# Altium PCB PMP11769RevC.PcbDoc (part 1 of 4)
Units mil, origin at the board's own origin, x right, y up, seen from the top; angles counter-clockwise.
Board outline 7800 x 8510 mil, 4 copper layers (Top, Inner Top, Inner Bottom, Bottom), stack 33.235 mil thick; 451 components, 226 nets, 1199 pads, 1742 vias.
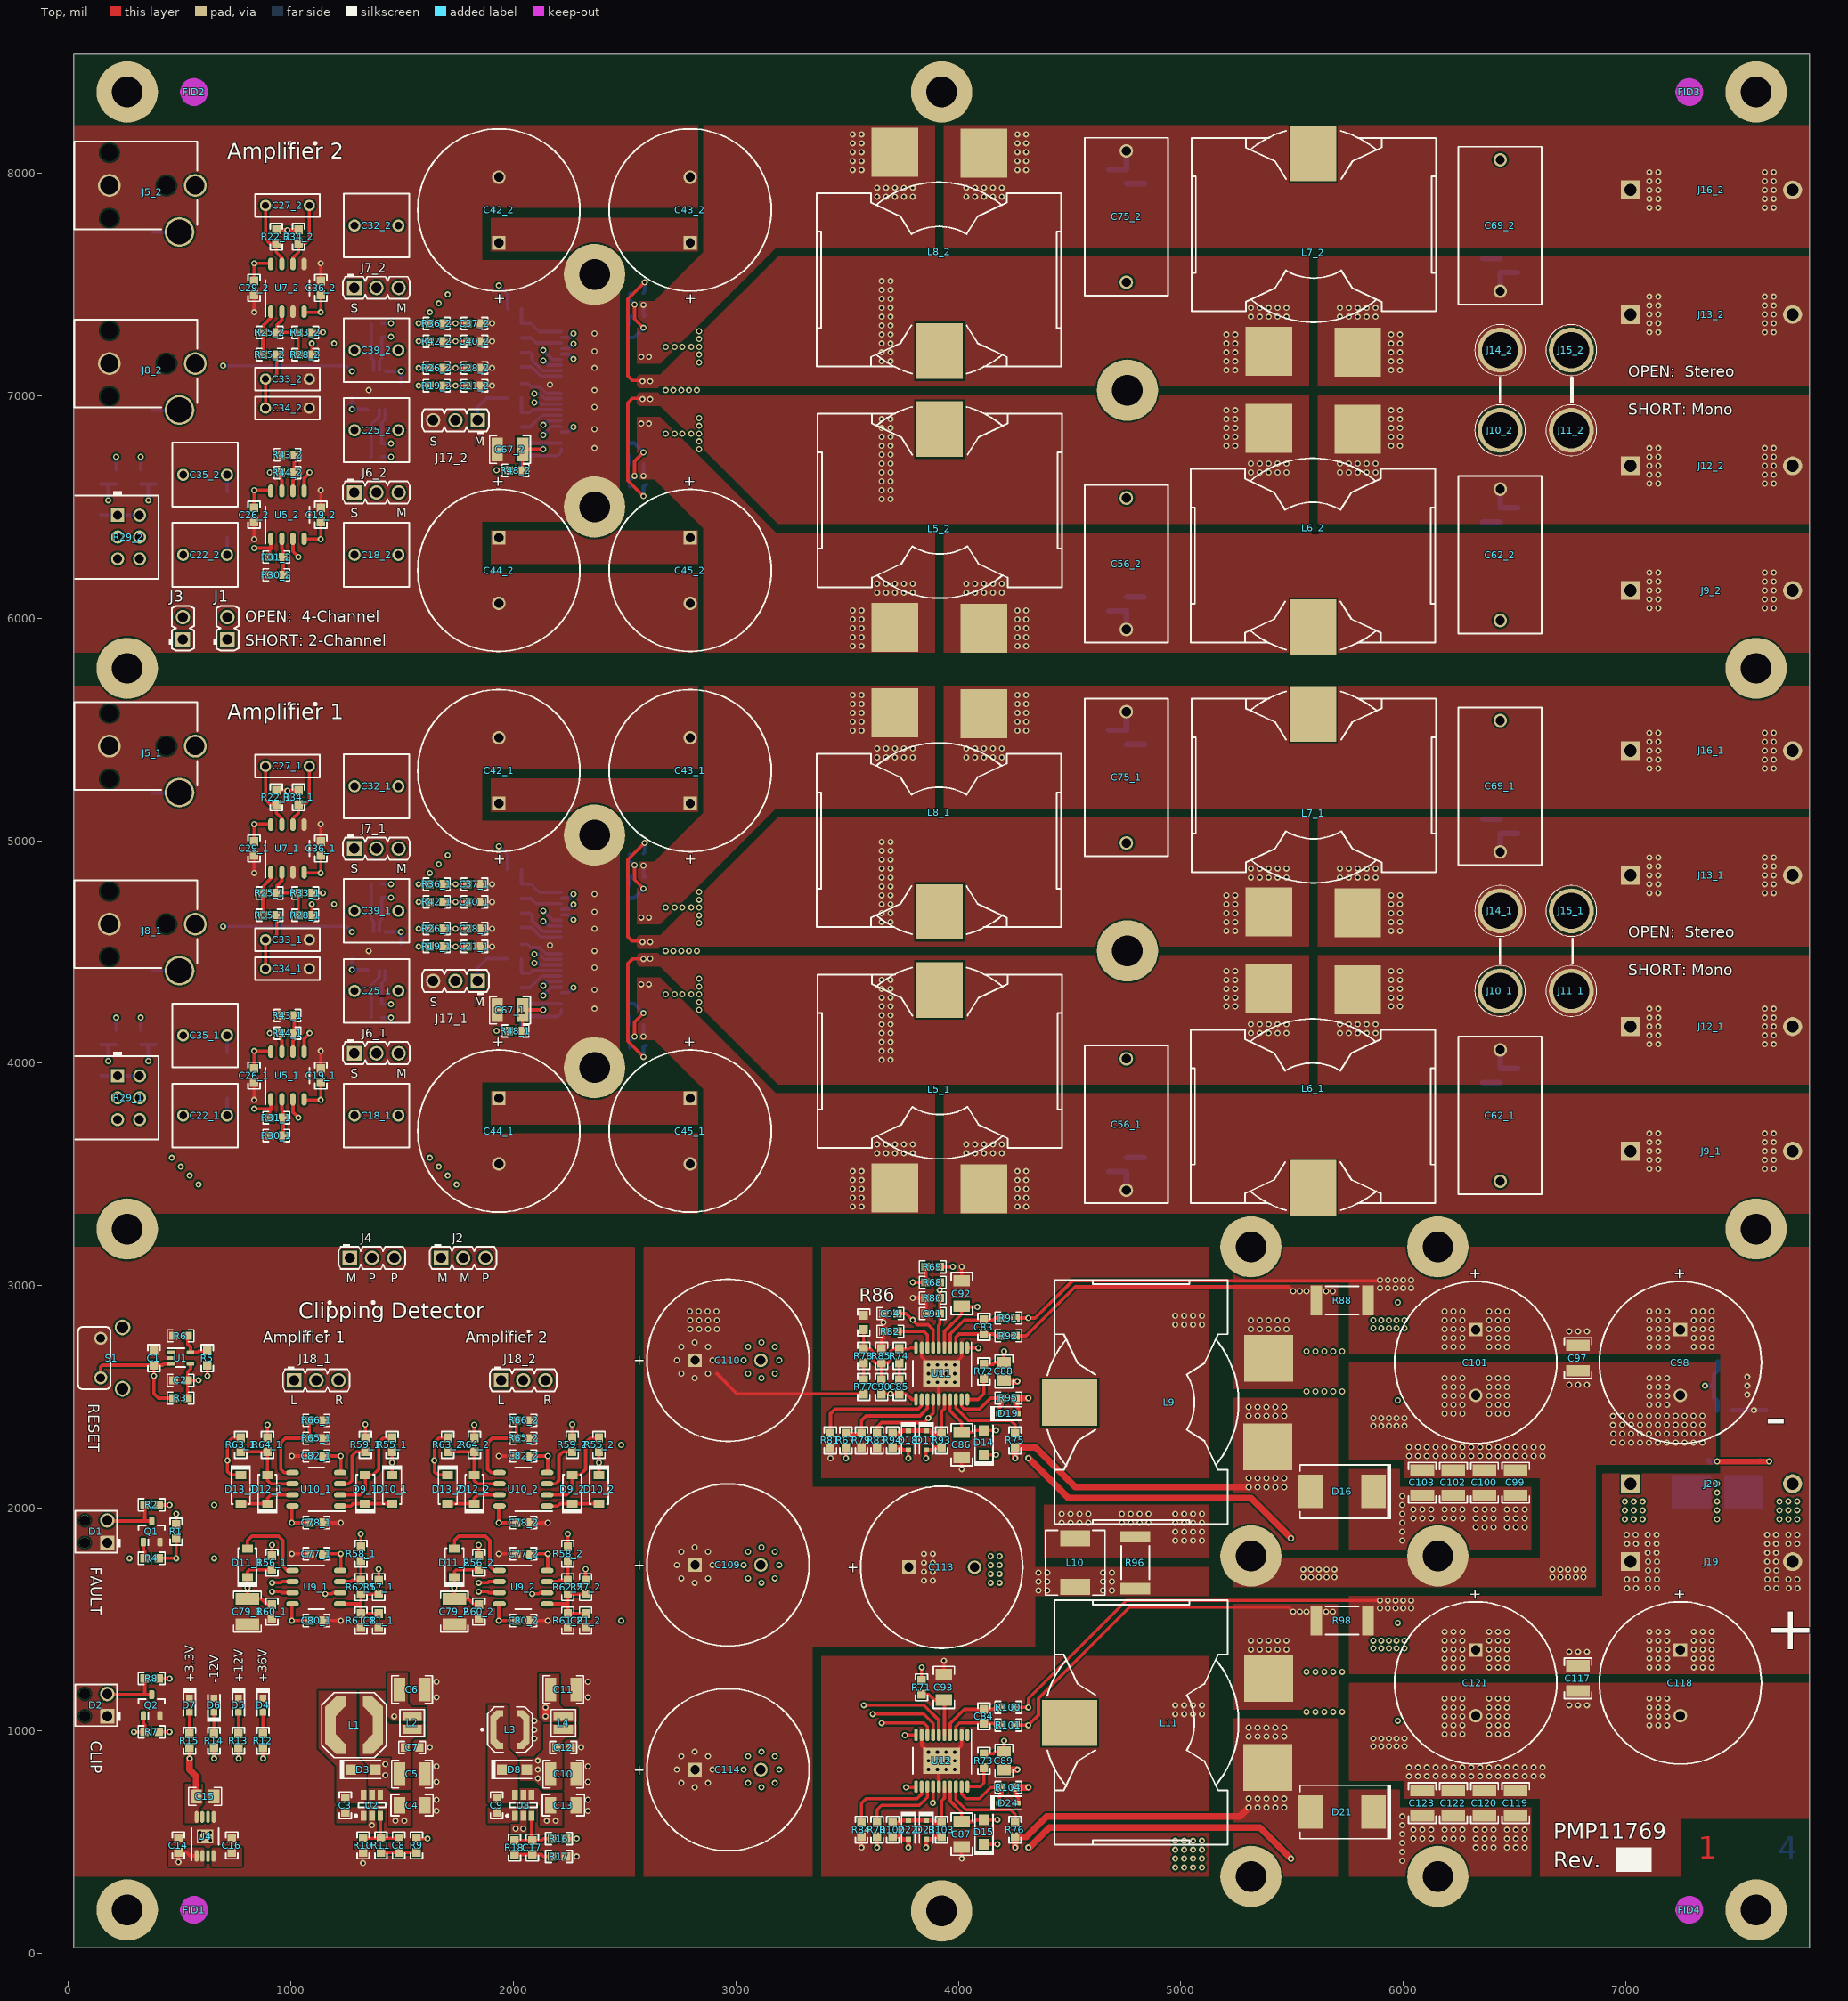
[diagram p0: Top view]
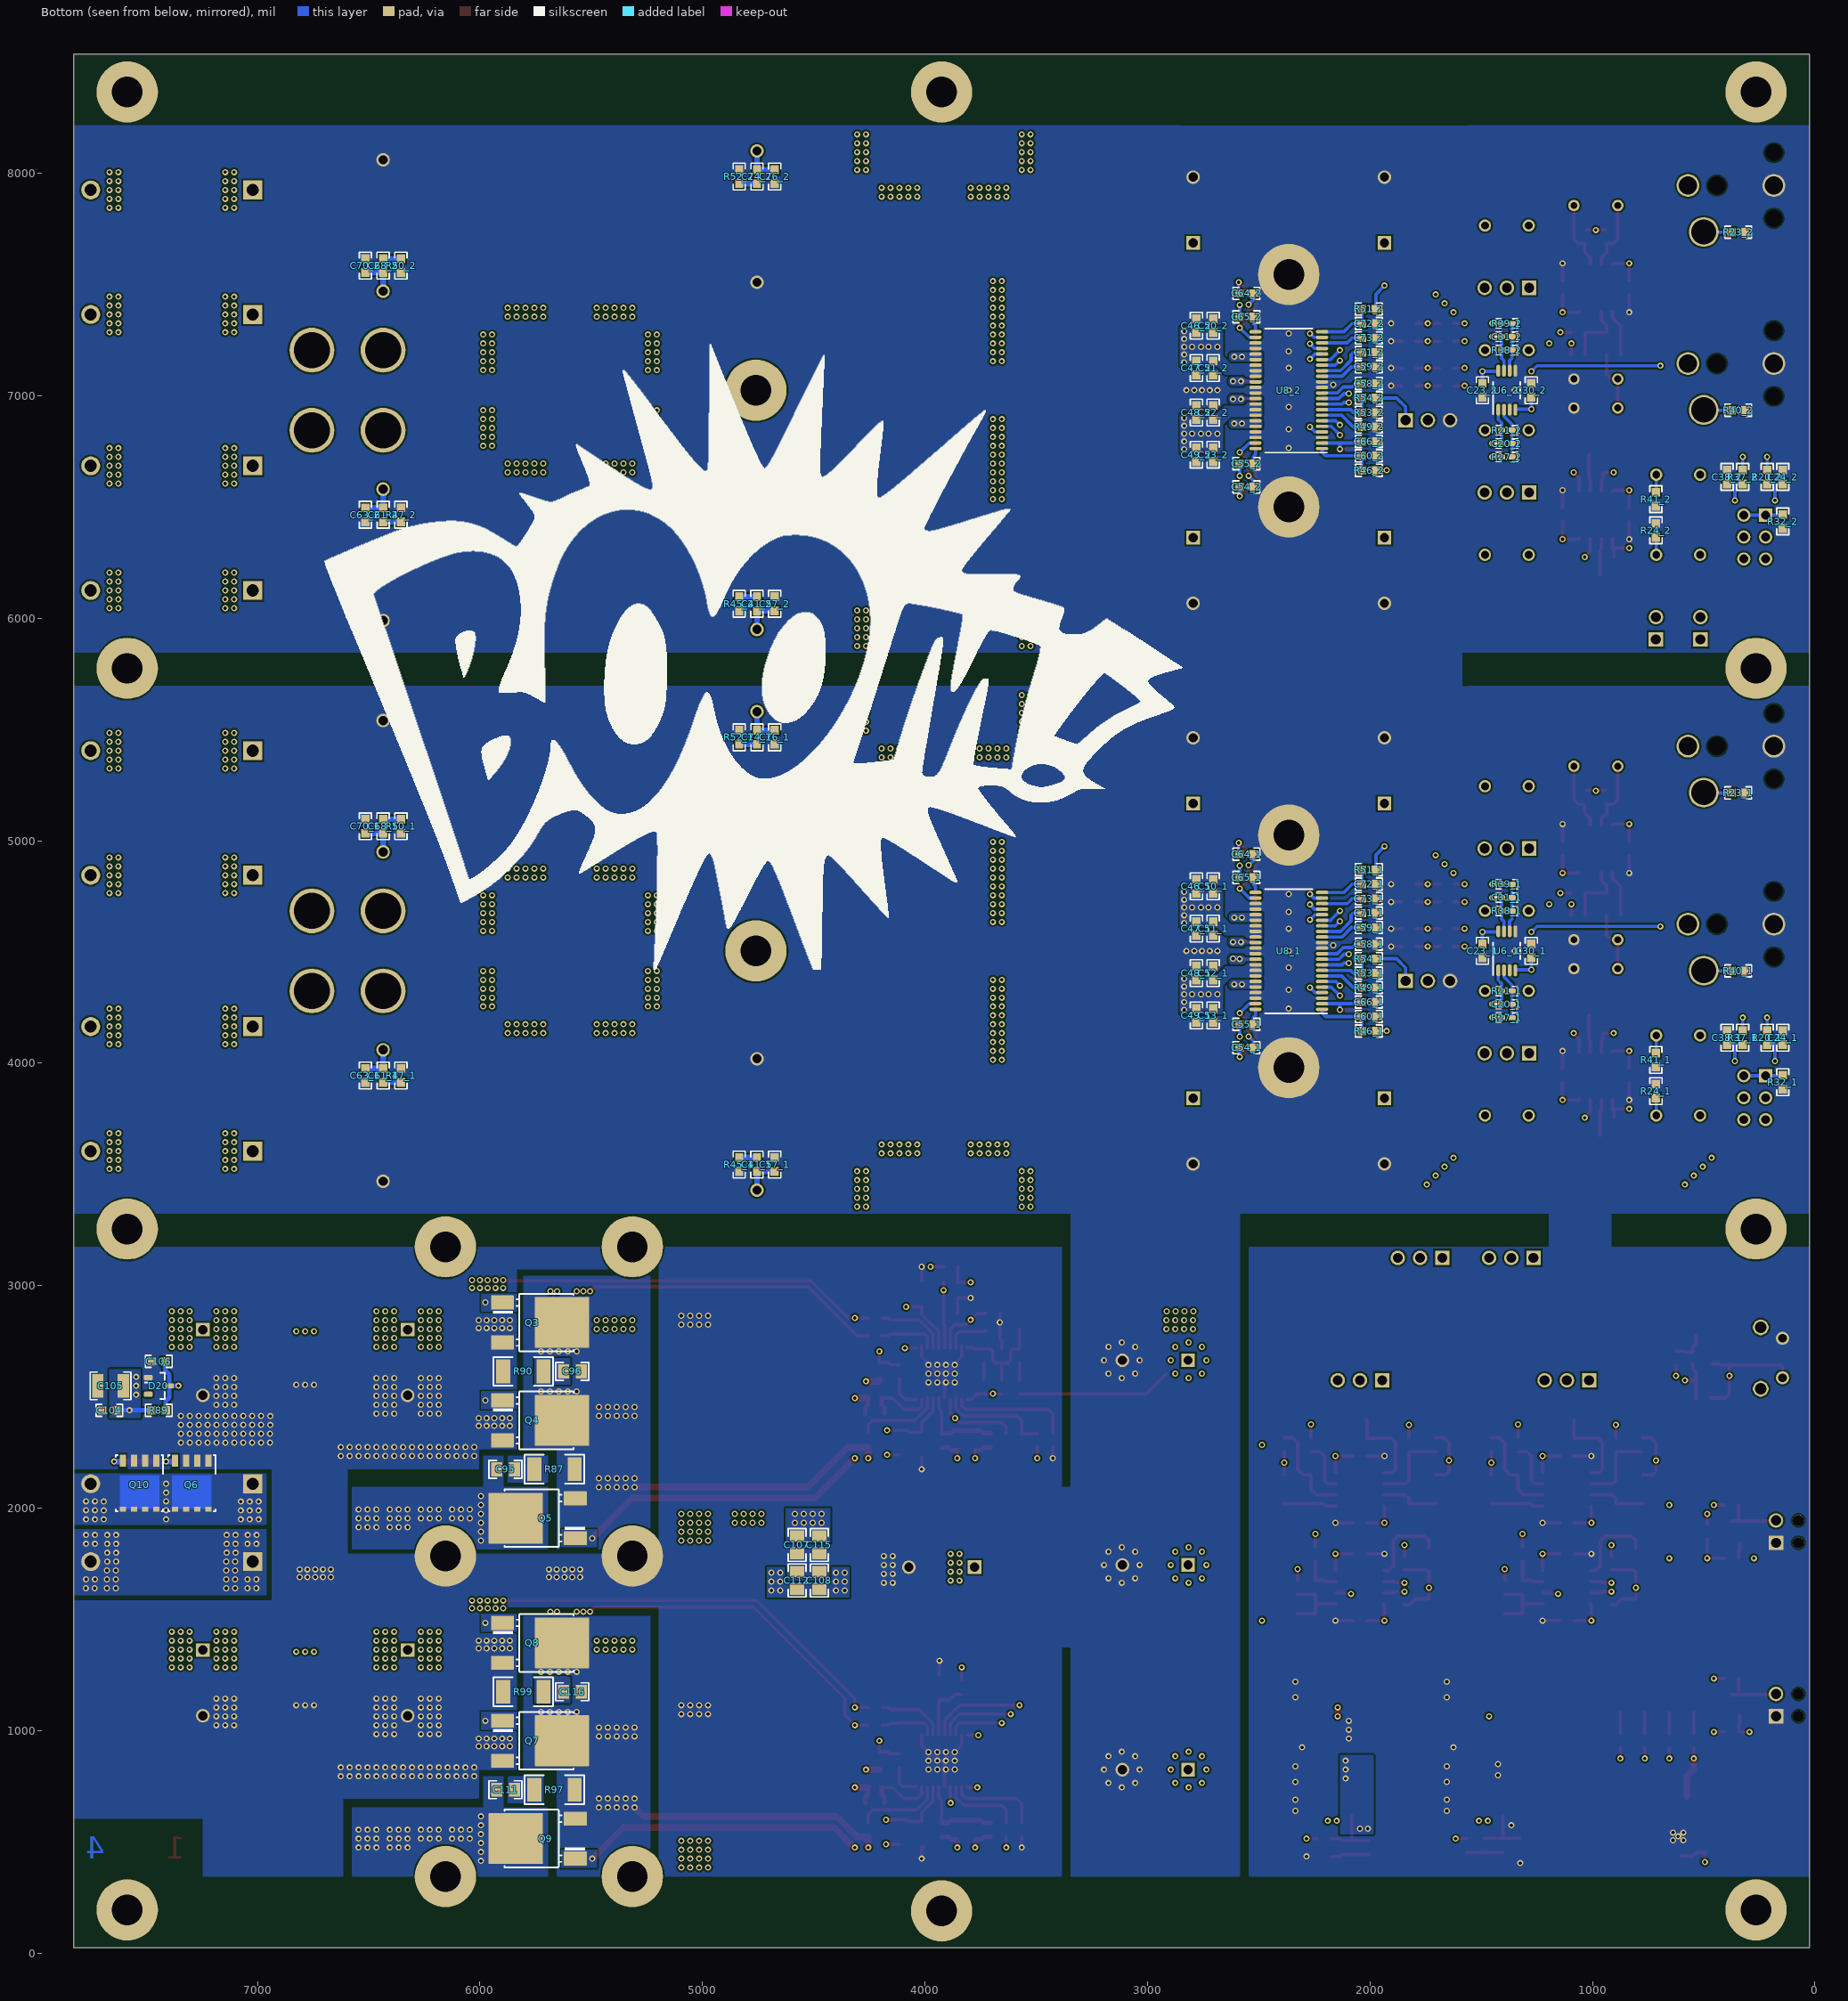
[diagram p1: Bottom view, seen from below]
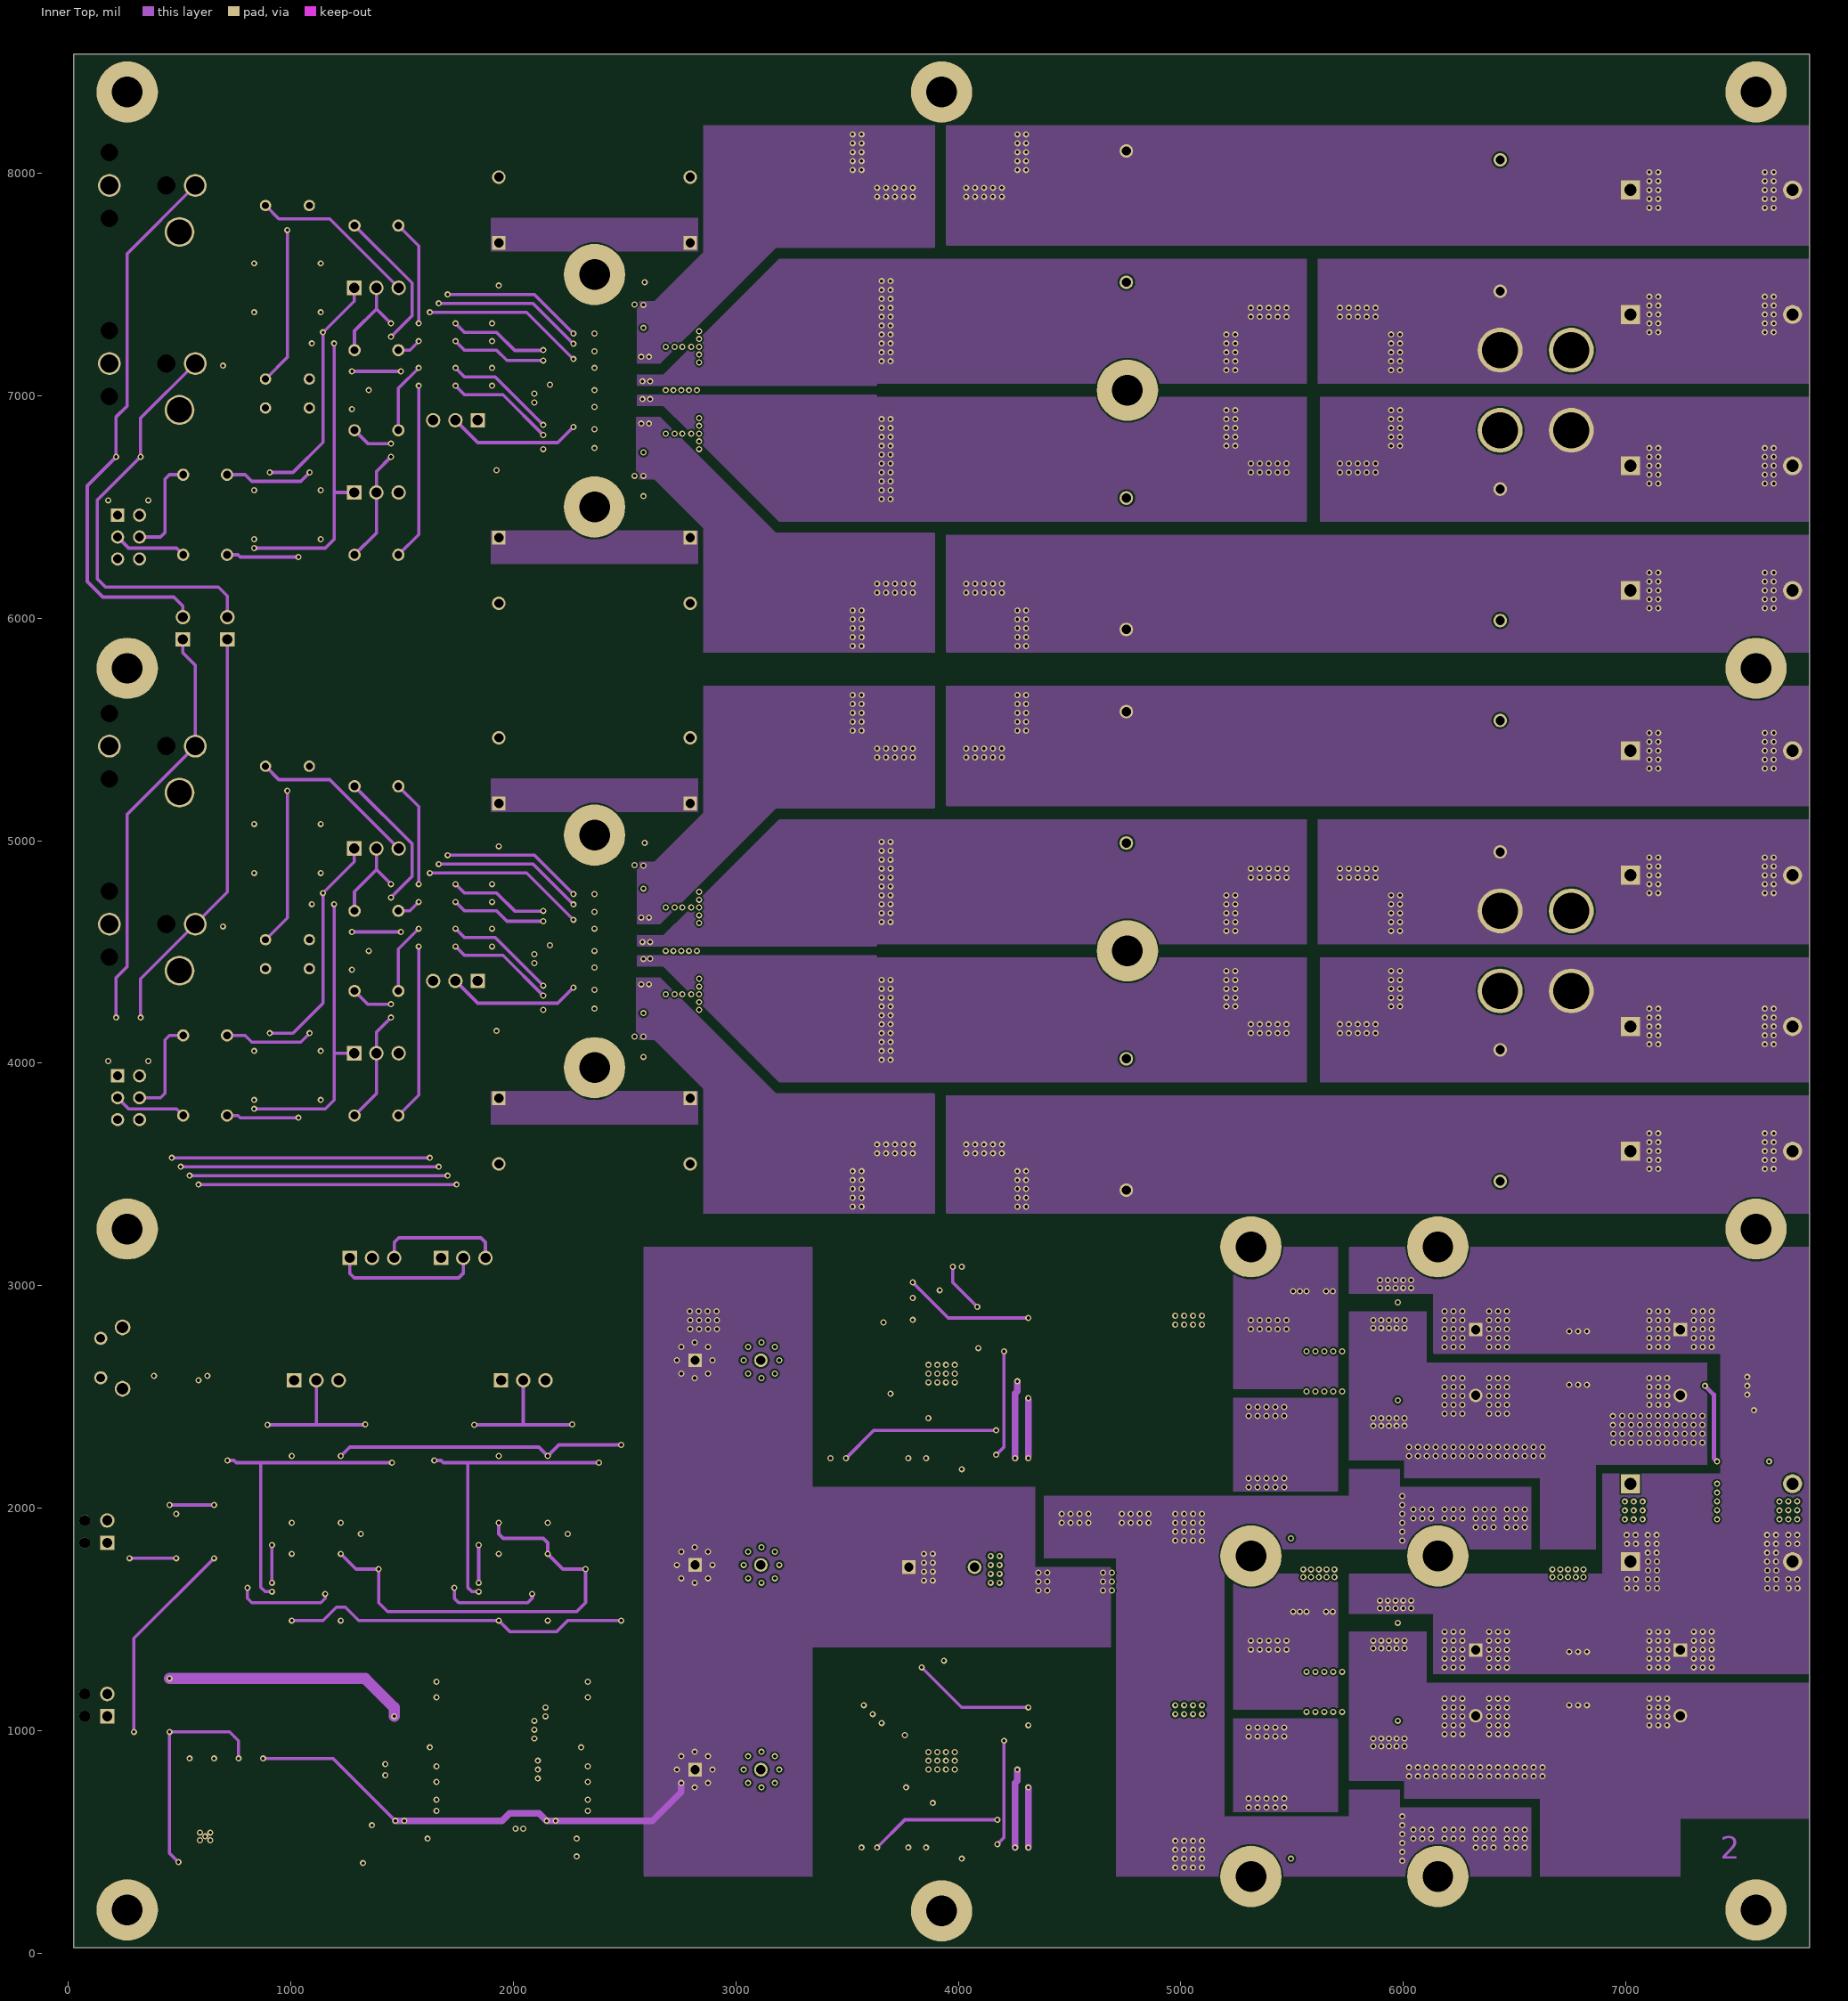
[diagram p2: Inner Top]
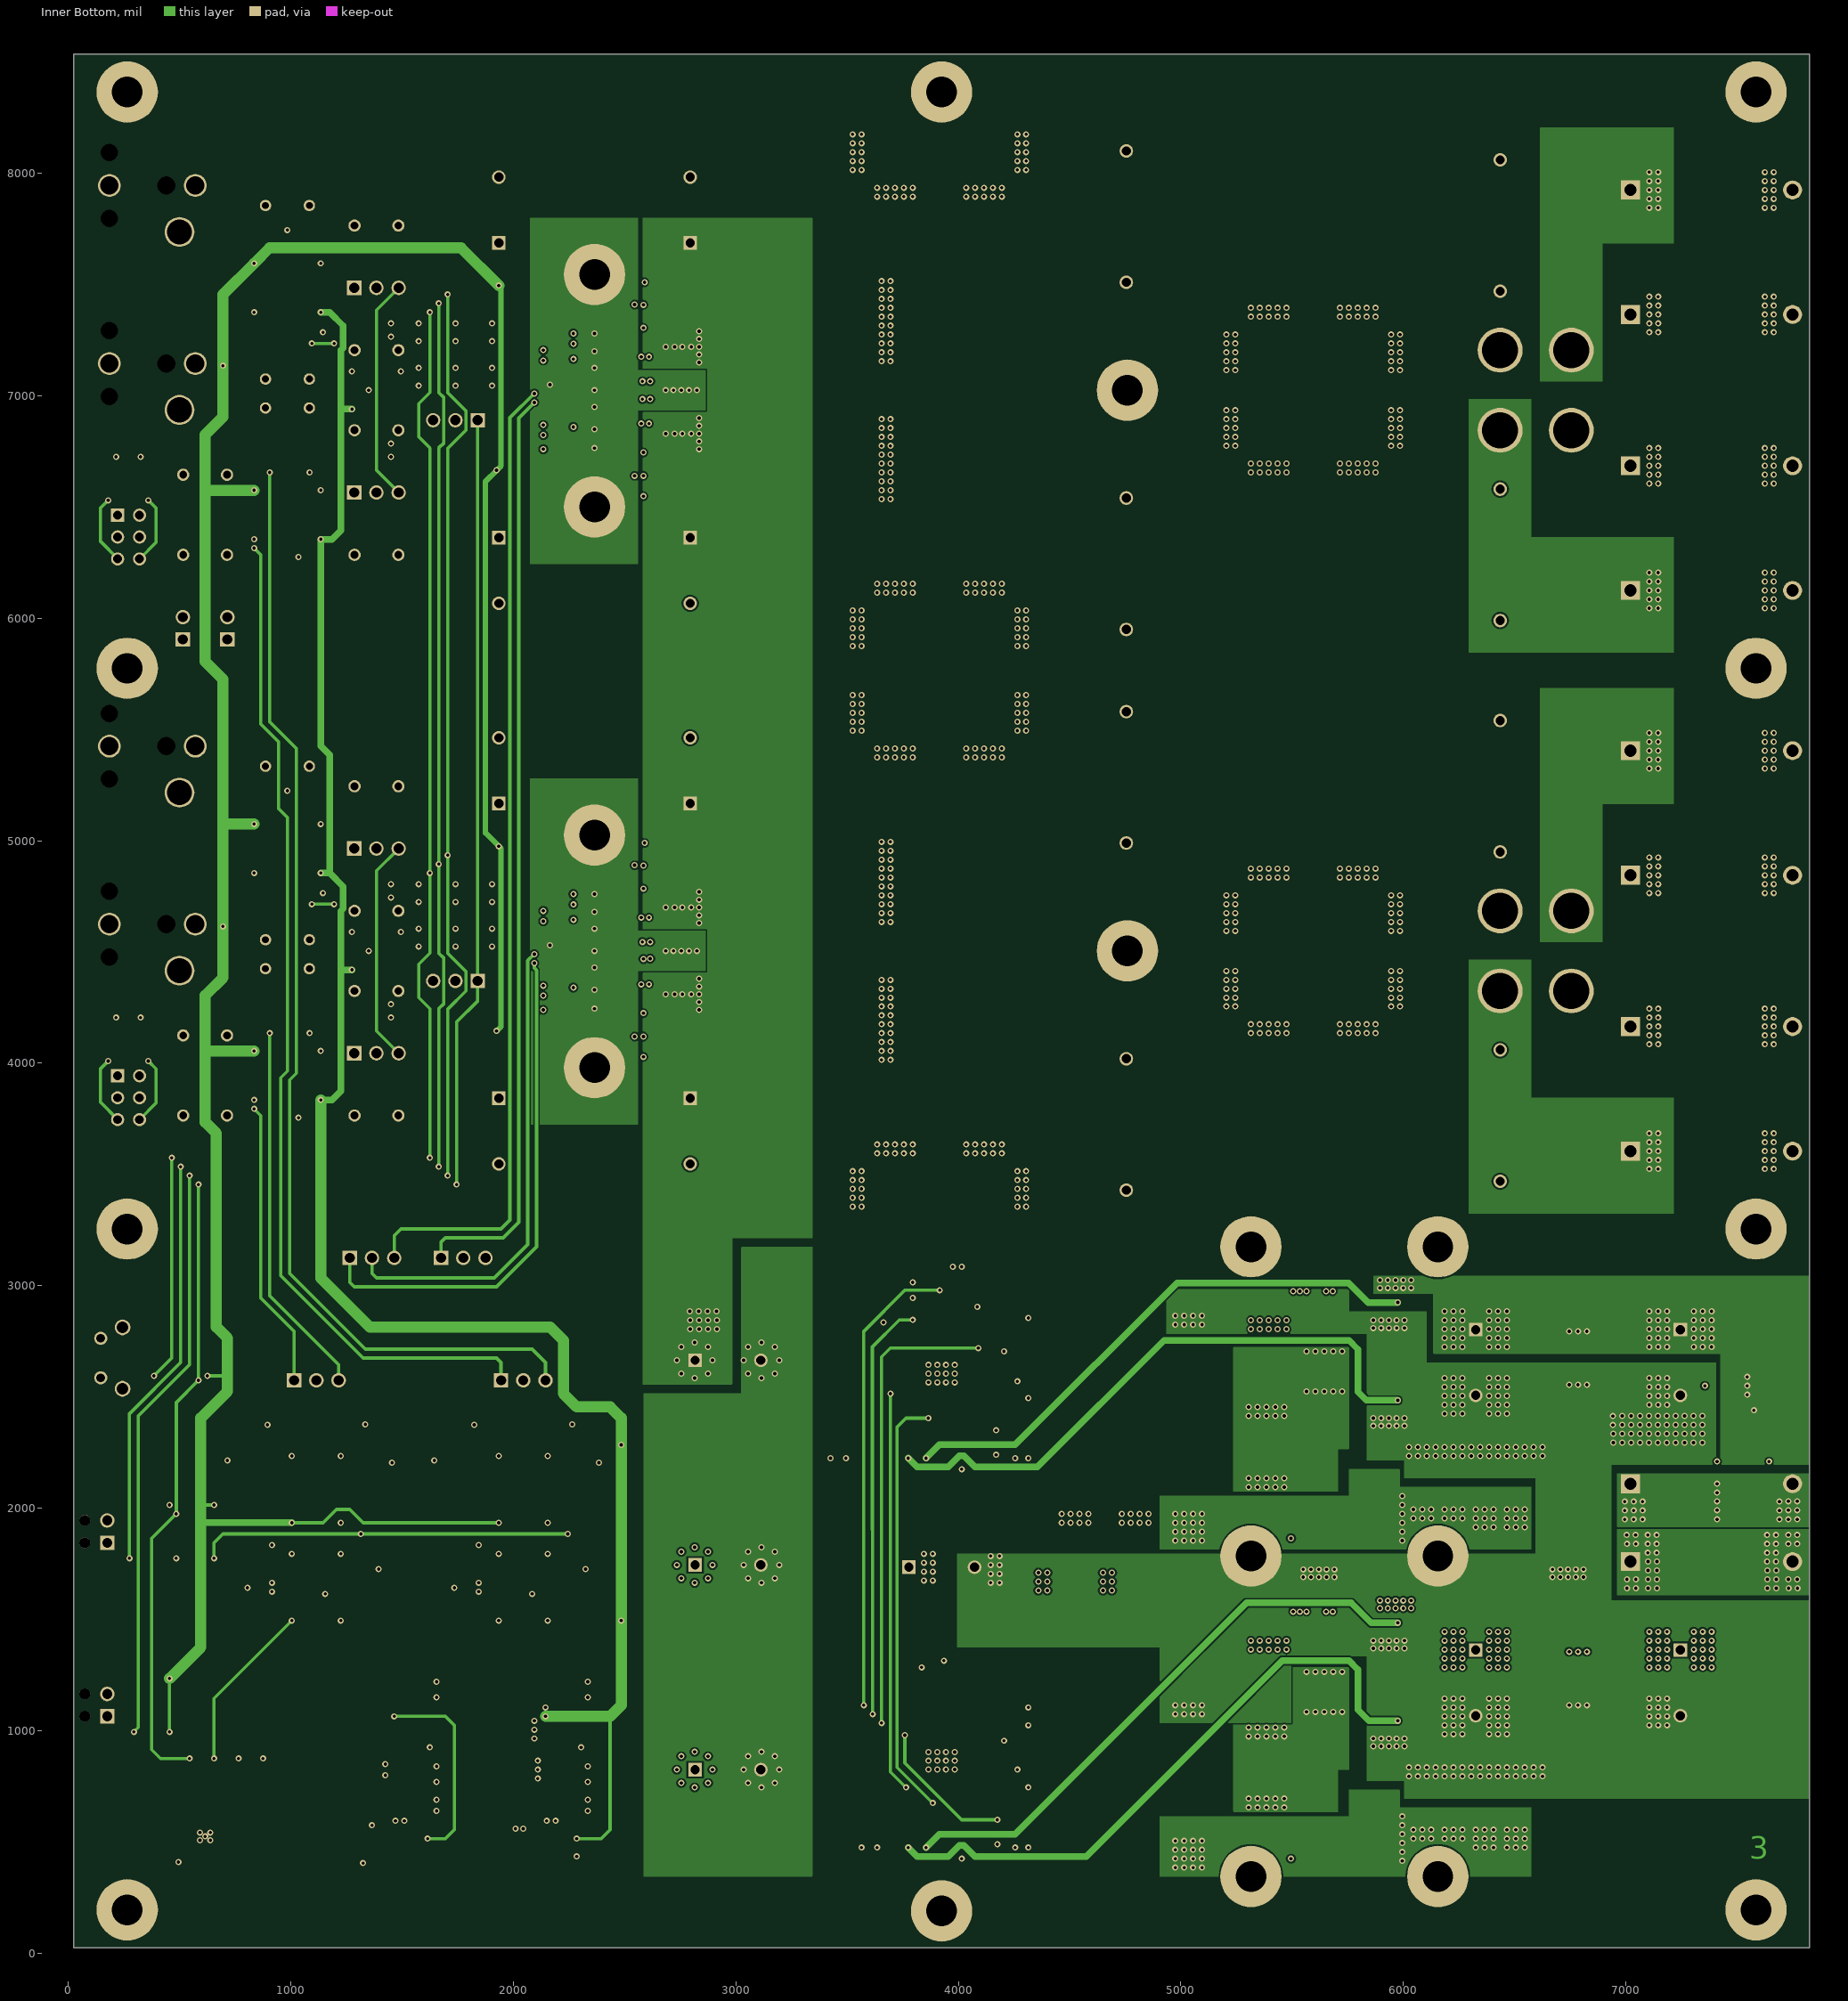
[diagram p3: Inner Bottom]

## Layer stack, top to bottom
Top Solder: solder mask 0.4, Solder Resist, Dk 3.5
Top: signal copper 1.4
Dielectric 1: core 12.6, FR-4, Dk 4.8
Inner Top: signal copper 1.4173
Dielectric 3: prepreg 5, Dk 4.2
Inner Bottom: signal copper 1.4173
Dielectric 2: core 10, Dk 4.2
Bottom: signal copper 1.4
Bottom Solder: solder mask 0.4, Solder Resist, Dk 3.5

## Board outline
25,25 25,8535 7825,8535 7825,25

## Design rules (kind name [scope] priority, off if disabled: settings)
Clearance [All] p1: gap=7.87
ComponentClearance [All] p1: gap=10 collisioncheckmode=3 verticalgap=10 showdistances=TRUE
DiffPairsRouting [All] p1: maxlimit=393.7 minlimit=4.92 mostfreqgap=5.91 toplayer_minwidth=15 toplayer_maxwidth=15 toplayer_prefwidth=15 midlayer1_minwidth=15 midlayer1_maxwidth=15 midlayer1_prefwidth=15 midlayer2_minwidth=15 midlayer2_maxwidth=15 midlayer2_prefwidth=15 bottomlayer_minwidth=15 bottomlayer_maxwidth=15 bottomlayer_prefwidth=15 maxuncoupledlength=500
FabricationTestPointUsage FabricationTestPointUsage_1 [All] p1: valid=0 allowmultiple=FALSE
FabricationTestpoint FabricationTestpoint_1 [All] p1: side=3 testpointundercomponent=TRUE minsize=40 maxsize=100 preferedsize=60 minholesize=0 maxholesize=40 preferedholesize=32 testpointgrid=1 allowsidetop=TRUE allowsidebottom=TRUE usegrid=TRUE gridtolerance=0.01
Height [All] p1: minheight=0 maxheight=1000.79 prefheight=500
HoleSize [All] p1: absolutevalues=TRUE maxlimit=236.22 minlimit=11.81 maxpercent=80.000 minpercent=20.000
HoleSize FabricationTestpoint [All] p2 off: absolutevalues=TRUE maxlimit=100 minlimit=1 maxpercent=80.000 minpercent=20.000
HoleSize FabricationTestPointUsage [All] p3 off: absolutevalues=TRUE maxlimit=100 minlimit=1 maxpercent=80.000 minpercent=20.000
MinimumAnnularRing [All] p1: minimumring=5.91
MinimumSolderMaskSliver [All] p1: minsoldermaskwidth=1
PlaneClearance [All] p1: clearance=19.68
PlaneConnect [All] p1: planeconnectstyle=Direct reliefexpansion=15.75 reliefentries=4 reliefconductorwidth=5.91 reliefairgap=5.91
PolygonConnect [All] p1: connectstyle=Direct reliefconductorwidth=5.91 reliefentries=4 polygonreliefangle="90 Angle" airgapwidth=10
RoomDefinition 2 [InComponentClass('2')] p1: confinementstyle=ConfineIn formatcopy=TRUE lockcomponents=FALSE outline -585,5825 7870,5825 7870,8235 -585,8235
RoomDefinition 1 [InComponentClass('1')] p2: confinementstyle=ConfineIn formatcopy=TRUE lockcomponents=FALSE outline -585,3305 7870,3305 7870,5715 -585,5715
RoutingCorners [All] p1: cornerstyle=45-Degree minsetback=49.21 maxsetback=49.21
RoutingVias [All] p1: holewidth=11.81 width=27.56 viastyle="Through Hole" minholewidth=11.81 minwidth=19.68 maxholewidth=39.37 maxwidth=59.06
SilkToSilkClearance [All] p1: silktosilkclearance=3.94
SilkToSolderMaskClearance SilkscreenOverComponentPads [IsPad] p1: minsilkscreentomaskgap=5 clearancetoexposedcopper=TRUE
SolderMaskExpansion [All] p1: expansion=2.95
UnpouredPolygon [All] p1: allowunpoured=FALSE
Width [All] p1: maxlimit=393.7 minlimit=4.92 preferedwidth=10 toplayer_minwidth=5.91 midlayer1_prefwidth=5.91 midlayer2_prefwidth=5.91 bottomlayer_minwidth=5.91 minimp=50.000000 maximp=50.000000 favimp=50.000000
17 further rules are at their usual default settings.

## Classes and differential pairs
channel class "PMP11769Revc - Clipping Detector": 1 2
channel class "PMP11769RevC - Amplifier": 1 2
net class OSC_IOP[1..2]: OSC_IOP1 OSC_IOP2
net class OSC_IOM[1..2]: OSC_IOM1 OSC_IOM2
net class IN_R[1..2]: IN_R1 IN_R2
net class IN_L[1..2]: IN_L1 IN_L2
component class 2: C18_2 C19_2 C20_2 C21_2 C22_2 C23_2 C24_2 C25_2 C26_2 C27_2 C28_2 C29_2 C30_2 C31_2 C32_2 C33_2 C34_2 C35_2 C36_2 C37_2 C38_2 C39_2 C40_2 C41_2 C42_2 C43_2 C44_2 C45_2 C46_2 C47_2 C48_2 C49_2 C50_2 C51_2 C52_2 C53_2 C54_2 C55_2 C56_2 C57_2 C58_2 C59_2 C60_2 C61_2 C62_2 C63_2 C64_2 C65_2 C66_2 C67_2 C68_2 C69_2 C70_2 C71_2 C72_2 C73_2 C74_2 C75_2 C76_2 J5_2 J6_2 J7_2 J8_2 J9_2 J10_2 J11_2 J12_2 J13_2 J14_2 J15_2 J16_2 J17_2 L5_2 L6_2 L7_2 L8_2 R19_2 R20_2 R21_2 R22_2 R23_2 R24_2 R25_2 R26_2 R27_2 R28_2 R29_2 R30_2 R31_2 R32_2 R33_2 R34_2 R35_2 R36_2 R37_2 R38_2 R39_2 R40_2 R41_2 R42_2 R43_2 R44_2 R45_2 R46_2 R47_2 R48_2 R49_2 R50_2 R51_2 R52_2 R53_2 R54_2 U5_2 U6_2 U7_2 U8_2
component class 1: C18_1 C19_1 C20_1 C21_1 C22_1 C23_1 C24_1 C25_1 C26_1 C27_1 C28_1 C29_1 C30_1 C31_1 C32_1 C33_1 C34_1 C35_1 C36_1 C37_1 C38_1 C39_1 C40_1 C41_1 C42_1 C43_1 C44_1 C45_1 C46_1 C47_1 C48_1 C49_1 C50_1 C51_1 C52_1 C53_1 C54_1 C55_1 C56_1 C57_1 C58_1 C59_1 C60_1 C61_1 C62_1 C63_1 C64_1 C65_1 C66_1 C67_1 C68_1 C69_1 C70_1 C71_1 C72_1 C73_1 C74_1 C75_1 C76_1 J5_1 J6_1 J7_1 J8_1 J9_1 J10_1 J11_1 J12_1 J13_1 J14_1 J15_1 J16_1 J17_1 L5_1 L6_1 L7_1 L8_1 R19_1 R20_1 R21_1 R22_1 R23_1 R24_1 R25_1 R26_1 R27_1 R28_1 R29_1 R30_1 R31_1 R32_1 R33_1 R34_1 R35_1 R36_1 R37_1 R38_1 R39_1 R40_1 R41_1 R42_1 R43_1 R44_1 R45_1 R46_1 R47_1 R48_1 R49_1 R50_1 R51_1 R52_1 R53_1 R54_1 U5_1 U6_1 U7_1 U8_1
net class BUFF_L[1..2]: BUFF_L1 BUFF_L2
net class BUFF_R[1..2]: BUFF_R1 BUFF_R2

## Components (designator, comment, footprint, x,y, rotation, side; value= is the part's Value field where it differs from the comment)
C1 "C1608X7R1E105K080AB" 0603 385,2675 r90 top
C2 "C1608X7R1H104K" 0603 505,2575 r0 top
C3 "C1608X7R1H104K" 0603 1245,665 r270 top
C4 "C3216X7R1H105K" 1206 1545,665 r0 top
C5 "C3225X7R1E106M" 1210 1545,805 r0 top
C6 "C3225X7R1E106M" 1210 1545,1185 r0 top
C7 "C1608X7R1H104K" 0603 1545,925 r180 top
C8 "C1608C0G1H221J" 0603 1485,485 r90 top
C9 "C1608X7R1H104K" 0603 1925,665 r270 top
C10 "C3225X7R1E106M" 1210 2225,805 r180 top
C11 "C3225X7R1E106M" 1210 2225,1185 r180 top
C12 "C1608X7R1H104K" 0603 2225,925 r0 top
C13 "C3216X7R1H105K" 1206 2225,665 r0 top
C14 "C1608X7R1E105K080AB" 0603 495,485 r90 top
C15 "C2012X7R1A475M" 0805_HV 615,705 r0 top
C16 "C1608X7R1H102K" 0603 735,485 r90 top
C17 "C1608C0G1H221J" 0603 2085,475 r90 top
C18_1 "R82CC4470Z330J" R82_720x720x1300 1385,3765 r180 top (schematic designator C18)
C18_2 "R82CC4470Z330J" R82_720x720x1300 1385,6285 r180 top (schematic designator C18)
C19_1 "C1608X7R1H104K" 0603 1135,3945 r90 top (schematic designator C19)
C19_2 "C1608X7R1H104K" 0603 1135,6465 r90 top (schematic designator C19)
C20_1 "C1005C0G1H220J050BA" 0402 1385,4265 r180 bottom (schematic designator C20)
C20_2 "C1005C0G1H220J050BA" 0402 1385,6785 r180 bottom (schematic designator C20)
C21_1 "C1608C0G1H101J" 0603 1825,4525 r0 top (schematic designator C21)
C21_2 "C1608C0G1H101J" 0603 1825,7045 r0 top (schematic designator C21)
C22_1 "R82CC4470Z330J" R82_720x720x1300 615,3765 r180 top (schematic designator C22)
C22_2 "R82CC4470Z330J" R82_720x720x1300 615,6285 r180 top (schematic designator C22)
C23_1 "C1608X7R1H104K" 0603 1495,4505 r270 bottom (schematic designator C23)
C23_2 "C1608X7R1H104K" 0603 1495,7025 r270 bottom (schematic designator C23)
C24_1 "C1608C0G1H101J" 0603 145,4115 r90 bottom (schematic designator C24)
C24_2 "C1608C0G1H101J" 0603 145,6635 r90 bottom (schematic designator C24)
C25_1 "R82CC4470Z330J" R82_720x720x1300 1385,4325 r180 top (schematic designator C25)
C25_2 "R82CC4470Z330J" R82_720x720x1300 1385,6845 r180 top (schematic designator C25)
C26_1 "C1608X7R1H104K" 0603 835,3945 r270 top (schematic designator C26)
C26_2 "C1608X7R1H104K" 0603 835,6465 r270 top (schematic designator C26)
C27_1 "R82DC3100DQ50J" R82_720x250x650 985,5335 r0 top (schematic designator C27)
C27_2 "R82DC3100DQ50J" R82_720x250x650 985,7855 r0 top (schematic designator C27)
C28_1 "C1608C0G1H101J" 0603 1825,4605 r0 top (schematic designator C28)
C28_2 "C1608C0G1H101J" 0603 1825,7125 r0 top (schematic designator C28)
C29_1 "C1608X7R1H104K" 0603 835,4965 r270 top (schematic designator C29)
C29_2 "C1608X7R1H104K" 0603 835,7485 r270 top (schematic designator C29)
C30_1 "C1608X7R1H104K" 0603 1275,4505 r90 bottom (schematic designator C30)
C30_2 "C1608X7R1H104K" 0603 1275,7025 r90 bottom (schematic designator C30)
C31_1 "C1005C0G1H220J050BA" 0402 1385,4745 r180 bottom (schematic designator C31)
C31_2 "C1005C0G1H220J050BA" 0402 1385,7265 r180 bottom (schematic designator C31)
C32_1 "R82CC4470Z330J" R82_720x720x1300 1385,5245 r180 top (schematic designator C32)
C32_2 "R82CC4470Z330J" R82_720x720x1300 1385,7765 r180 top (schematic designator C32)
C33_1 "R82DC3220DQ60J" R82_720x250x650 985,4555 r0 top (schematic designator C33)
C33_2 "R82DC3220DQ60J" R82_720x250x650 985,7075 r0 top (schematic designator C33)
C34_1 "R82DC3150AA60J" R82_720x250x650 985,4425 r0 top (schematic designator C34)
C34_2 "R82DC3150AA60J" R82_720x250x650 985,6945 r0 top (schematic designator C34)
C35_1 "R82CC4470Z330J" R82_720x720x1300 615,4125 r180 top (schematic designator C35)
C35_2 "R82CC4470Z330J" R82_720x720x1300 615,6645 r180 top (schematic designator C35)
C36_1 "C1608X7R1H104K" 0603 1135,4965 r90 top (schematic designator C36)
C36_2 "C1608X7R1H104K" 0603 1135,7485 r90 top (schematic designator C36)
C37_1 "C1608C0G1H101J" 0603 1825,4805 r0 top (schematic designator C37)
C37_2 "C1608C0G1H101J" 0603 1825,7325 r0 top (schematic designator C37)
C38_1 "C1608C0G1H101J" 0603 395,4115 r90 bottom (schematic designator C38)
C38_2 "C1608C0G1H101J" 0603 395,6635 r90 bottom (schematic designator C38)
C39_1 "R82CC4470Z330J" R82_720x720x1300 1385,4685 r180 top (schematic designator C39)
C39_2 "R82CC4470Z330J" R82_720x720x1300 1385,7205 r180 top (schematic designator C39)
C40_1 "C1608C0G1H101J" 0603 1825,4725 r0 top (schematic designator C40)
C40_2 "C1608C0G1H101J" 0603 1825,7245 r0 top (schematic designator C40)
C41_1 "C1608X7R1H103K" 0603 4755,3545 r90 bottom (schematic designator C41)
C41_2 "C1608X7R1H103K" 0603 4755,6065 r90 bottom (schematic designator C41)
C42_1 "UPW1H821MHD6" PW_1800x2000 1935,5315 r90 top (schematic designator C42)
C42_2 "UPW1H821MHD6" PW_1800x2000 1935,7835 r90 top (schematic designator C42)
C43_1 "UPW1H821MHD6" PW_1800x2000 2795,5315 r90 top (schematic designator C43)
C43_2 "UPW1H821MHD6" PW_1800x2000 2795,7835 r90 top (schematic designator C43)
C44_1 "UPW1H821MHD6" PW_1800x2000 1935,3695 r270 top (schematic designator C44)
C44_2 "UPW1H821MHD6" PW_1800x2000 1935,6215 r270 top (schematic designator C44)
C45_1 "UPW1H821MHD6" PW_1800x2000 2795,3695 r270 top (schematic designator C45)
C45_2 "UPW1H821MHD6" PW_1800x2000 2795,6215 r270 top (schematic designator C45)
C46_1 "UMK107AB7105KA-T" 0603 2780,4795 r90 bottom (schematic designator C46)
C46_2 "UMK107AB7105KA-T" 0603 2780,7315 r90 bottom (schematic designator C46)
C47_1 "UMK107AB7105KA-T" 0603 2780,4605 r270 bottom (schematic designator C47)
C47_2 "UMK107AB7105KA-T" 0603 2780,7125 r270 bottom (schematic designator C47)
C48_1 "UMK107AB7105KA-T" 0603 2780,4405 r90 bottom (schematic designator C48)
C48_2 "UMK107AB7105KA-T" 0603 2780,6925 r90 bottom (schematic designator C48)
C49_1 "UMK107AB7105KA-T" 0603 2780,4215 r270 bottom (schematic designator C49)
C49_2 "UMK107AB7105KA-T" 0603 2780,6735 r270 bottom (schematic designator C49)
C50_1 "UMK107AB7105KA-T" 0603 2705,4795 r90 bottom (schematic designator C50)
C50_2 "UMK107AB7105KA-T" 0603 2705,7315 r90 bottom (schematic designator C50)
C51_1 "UMK107AB7105KA-T" 0603 2705,4605 r270 bottom (schematic designator C51)
C51_2 "UMK107AB7105KA-T" 0603 2705,7125 r270 bottom (schematic designator C51)
C52_1 "UMK107AB7105KA-T" 0603 2705,4405 r90 bottom (schematic designator C52)
C52_2 "UMK107AB7105KA-T" 0603 2705,6925 r90 bottom (schematic designator C52)
C53_1 "UMK107AB7105KA-T" 0603 2705,4215 r270 bottom (schematic designator C53)
C53_2 "UMK107AB7105KA-T" 0603 2705,6735 r270 bottom (schematic designator C53)
C54_1 "GRM188R71H333KA61D" 0603 2555,4070 r0 bottom (schematic designator C54)
C54_2 "GRM188R71H333KA61D" 0603 2555,6590 r0 bottom (schematic designator C54)
C55_1 "GRM188R71H333KA61D" 0603 2555,4175 r0 bottom (schematic designator C55)
C55_2 "GRM188R71H333KA61D" 0603 2555,6695 r0 bottom (schematic designator C55)
C56_1 "PHE426HB7100JR06" PHE426_1800x950x1750 4755,3725 r90 top (schematic designator C56)
C56_2 "PHE426HB7100JR06" PHE426_1800x950x1750 4755,6245 r90 top (schematic designator C56)
C57_1 "C1608C0G2A102J" 0603 4675,3545 r90 bottom (schematic designator C57)
C57_2 "C1608C0G2A102J" 0603 4675,6065 r90 bottom (schematic designator C57)
C58_1 "C1608X7R1E105K080AB" 0603 2005,4535 r180 bottom (schematic designator C58)
C58_2 "C1608X7R1E105K080AB" 0603 2005,7055 r180 bottom (schematic designator C58)
C59_1 "C1608X7R1E105K080AB" 0603 2005,4610 r180 bottom (schematic designator C59)
C59_2 "C1608X7R1E105K080AB" 0603 2005,7130 r180 bottom (schematic designator C59)
C60_1 "C1608X7R1H104K" 0603 2005,4210 r0 bottom (schematic designator C60)
C60_2 "C1608X7R1H104K" 0603 2005,6730 r0 bottom (schematic designator C60)
C61_1 "C1608X7R1H103K" 0603 6435,3945 r270 bottom (schematic designator C61)
C61_2 "C1608X7R1H103K" 0603 6435,6465 r270 bottom (schematic designator C61)
C62_1 "PHE426HB7100JR06" PHE426_1800x950x1750 6435,3765 r270 top (schematic designator C62)
C62_2 "PHE426HB7100JR06" PHE426_1800x950x1750 6435,6285 r270 top (schematic designator C62)
C63_1 "C1608C0G2A102J" 0603 6515,3945 r270 bottom (schematic designator C63)
C63_2 "C1608C0G2A102J" 0603 6515,6465 r270 bottom (schematic designator C63)
C64_1 "GRM188R71H333KA61D" 0603 2555,4940 r180 bottom (schematic designator C64)
C64_2 "GRM188R71H333KA61D" 0603 2555,7460 r180 bottom (schematic designator C64)
C65_1 "GRM188R71H333KA61D" 0603 2555,4835 r180 bottom (schematic designator C65)
C65_2 "GRM188R71H333KA61D" 0603 2555,7355 r180 bottom (schematic designator C65)
C66_1 "C1608X7R1H104K" 0603 2005,4275 r0 bottom (schematic designator C66)
C66_2 "C1608X7R1H104K" 0603 2005,6795 r0 bottom (schematic designator C66)
C67_1 "C3225X7R1E106M" 1210 1985,4238.54 r180 top (schematic designator C67)
C67_2 "C3225X7R1E106M" 1210 1985,6758.54 r180 top (schematic designator C67)
C68_1 "C1608X7R1H103K" 0603 6435,5065 r90 bottom (schematic designator C68)
C68_2 "C1608X7R1H103K" 0603 6435,7585 r90 bottom (schematic designator C68)
C69_1 "PHE426HB7100JR06" PHE426_1800x950x1750 6435,5245 r90 top (schematic designator C69)
C69_2 "PHE426HB7100JR06" PHE426_1800x950x1750 6435,7765 r90 top (schematic designator C69)
C70_1 "C1608C0G2A102J" 0603 6515,5065 r90 bottom (schematic designator C70)
C70_2 "C1608C0G2A102J" 0603 6515,7585 r90 bottom (schematic designator C70)
C71_1 "C1608X7R1E105K080AB" 0603 2005,4675 r0 bottom (schematic designator C71)
C71_2 "C1608X7R1E105K080AB" 0603 2005,7195 r0 bottom (schematic designator C71)
C72_1 "C1608X7R1H104K" 0603 2005,4805 r0 bottom (schematic designator C72)
C72_2 "C1608X7R1H104K" 0603 2005,7325 r0 bottom (schematic designator C72)
C73_1 "C1608X7R1H104K" 0603 2005,4740 r180 bottom (schematic designator C73)
C73_2 "C1608X7R1H104K" 0603 2005,7260 r180 bottom (schematic designator C73)
C74_1 "C1608X7R1H103K" 0603 4755,5465 r270 bottom (schematic designator C74)
C74_2 "C1608X7R1H103K" 0603 4755,7985 r270 bottom (schematic designator C74)
C75_1 "PHE426HB7100JR06" PHE426_1800x950x1750 4755,5285 r270 top (schematic designator C75)
C75_2 "PHE426HB7100JR06" PHE426_1800x950x1750 4755,7805 r270 top (schematic designator C75)
C76_1 "C1608C0G2A102J" 0603 4675,5465 r270 bottom (schematic designator C76)
C76_2 "C1608C0G2A102J" 0603 4675,7985 r270 bottom (schematic designator C76)
C77_1 "C1608X7R1H104K" 0603 1115,1795 r180 top (schematic designator C77)
C77_2 "C1608X7R1H104K" 0603 2045,1795 r180 top (schematic designator C77)
C78_1 "C1608X7R1H104K" 0603 1115,1935 r0 top (schematic designator C78)
C78_2 "C1608X7R1H104K" 0603 2045,1935 r0 top (schematic designator C78)
C79_1 "C3225X7R1E106M" 1210 805,1535 r270 top (schematic designator C79)
C79_2 "C3225X7R1E106M" 1210 1735,1535 r270 top (schematic designator C79)
C80_1 "C1608X7R1H104K" 0603 1115,1495 r0 top (schematic designator C80)
C80_2 "C1608X7R1H104K" 0603 2045,1495 r0 top (schematic designator C80)
C81_1 "C1608X7R1H104K" 0603 1395,1495 r90 top (schematic designator C81)
C81_2 "C1608X7R1H104K" 0603 2325,1495 r90 top (schematic designator C81)
C82_1 "C1608X7R1H104K" 0603 1115,2235 r180 top (schematic designator C82)
C82_2 "C1608X7R1H104K" 0603 2045,2235 r180 top (schematic designator C82)
C83 "C1608X7R1H221K" 0603 4115,2815 r270 top
C84 "C1608X7R1H221K" 0603 4115,1065 r270 top
C85 "C1608X7R1H473K" 0603 3735,2545 r90 top
C86 "C3216X7R1C475M" 1206 4015,2285 r270 top
C87 "C3216X7R1C475M" 1206 4015,535 r270 top
C88 "C2012X7R1E224K" 0805_HV 4205,2615 r270 top
C89 "C2012X7R1E224K" 0805_HV 4205,865 r270 top
C90 "C1608X7R1H102K" 0603 3655,2545 r90 top
C91 "C1608C0G1H101J" 0603 3885,2875 r180 top
C92 "C3216X7R1H105K" 1206 4015,2965 r270 top
C93 "C3216X7R1H105K" 1206 3935,1195 r270 top
C94 "GCM188R70J225KE22D" 0603 3695,2875 r180 top
C95 "C2012X7R2A102M" 0805_HV 5885,2175 r0 bottom
C96 "C2012X7R2A102M" 0805_HV 5585,2615 r0 bottom
C97 "CGA6P3X7R1H475K250AB" 1210 6785,2675 r270 top
C98 "UPW1V182MHD6" PW_1800x2000 7245,2655 r270 top
C99 "CGA6P3X7R1H475K250AB" 1210 6505,2115 r90 top
C100 "CGA6P3X7R1H475K250AB" 1210 6365,2115 r90 top
C101 "UPW1V182MHD6" PW_1800x2000 6325,2655 r270 top
C102 "CGA6P3X7R1H475K250AB" 1210 6225,2115 r90 top
C103 "CGA6P3X7R1H475K250AB" 1210 6085,2115 r90 top
C104 "C1608X7R1H104K" 0603 7665,2440 r0 bottom
C105 "CGA6P3X7R1H475K250AB" 1210 7660,2550 r0 bottom
C106 "C1608X7R1H104K" 0603 7443.5,2660 r180 bottom
C107 "C2012X7R2A104K125AA" 0805_HV 4575,1835 r90 bottom
C108 "C2012X7R2A104K125AA" 0805_HV 4475,1675 r90 bottom
C109 "UPW1H821MHD6" PW_1800x2000 2965,1745 r0 top
C110 "UPW1H821MHD6" PW_1800x2000 2965,2665 r0 top
C111 "C2012X7R2A102M" 0805_HV 5885,735 r0 bottom
C112 "C2012X7R2A102M" 0805_HV 4575,1675 r90 bottom
C113 "UPW1H821MHD6" PW_1800x2000 3925,1735 r0 top
C114 "UPW1H821MHD6" PW_1800x2000 2965,825 r0 top
C115 "C2012X7R2A102M" 0805_HV 4475,1835 r90 bottom
C116 "C2012X7R2A102M" 0805_HV 5585,1175 r0 bottom
C117 "CGA6P3X7R1H475K250AB" 1210 6785,1235 r270 top
C118 "UPW1V182MHD6" PW_1800x2000 7245,1215 r270 top
C119 "CGA6P3X7R1H475K250AB" 1210 6505,675 r90 top
C120 "CGA6P3X7R1H475K250AB" 1210 6365,675 r90 top
C121 "UPW1V182MHD6" PW_1800x2000 6325,1215 r270 top
C122 "CGA6P3X7R1H475K250AB" 1210 6225,675 r90 top
C123 "CGA6P3X7R1H475K250AB" 1210 6085,675 r90 top
D1 "551-0303F" 551-0403_Red 125,1895 r180 top
D2 "551-0303F" 551-0403_Red 125,1115 r180 top
D3 "PMEG6010" SOD-123F 1325,825 r0 top
D4 "150060GS75000" WL-SMCW_GREEN 875,1115 r270 top
D5 "150060GS75000" WL-SMCW_GREEN 765,1115 r270 top
D6 "150060GS75000" WL-SMCW_GREEN 655,1115 r90 top
D7 "150060GS75000" WL-SMCW_GREEN 545,1115 r270 top
D8 "PMEG6010" SOD-123F 2005,825 r0 top
D9_1 "1N4148" SOD-123FL 1335,2085 r90 top (schematic designator D9)
D9_2 "1N4148" SOD-123FL 2265,2085 r90 top (schematic designator D9)
D10_1 "1N4148" SOD-123FL 1455,2085 r270 top (schematic designator D10)
D10_2 "1N4148" SOD-123FL 2385,2085 r270 top (schematic designator D10)
D11_1 "1N4148" SOD-123FL 805,1755 r90 top (schematic designator D11)
D11_2 "1N4148" SOD-123FL 1735,1755 r90 top (schematic designator D11)
D12_1 "1N4148" SOD-123FL 895,2085 r90 top (schematic designator D12)
D12_2 "1N4148" SOD-123FL 1825,2085 r90 top (schematic designator D12)
D13_1 "1N4148" SOD-123FL 775,2085 r270 top (schematic designator D13)
D13_2 "1N4148" SOD-123FL 1705,2085 r270 top (schematic designator D13)
D14 "PMEG6010" SOD-123F 4115,2295 r90 top
D15 "PMEG6010" SOD-123F 4115,545 r90 top
D16 "SS63" SMC 5725,2075 r180 top
D17 "BAT54" sod-323 3855,2305 r270 top
D18 "BAT54" sod-323 3775,2305 r270 top
D19 "BAT54" sod-323 4225,2425 r0 top
D20 "BZX84C15LT1G" SOT-23 7443.5,2550 r180 bottom
D21 "SS63" SMC 5725,635 r180 top
D22 "BAT54" sod-323 3775,555 r270 top
D23 "BAT54" sod-323 3855,555 r270 top
D24 "BAT54" sod-323 4225,675 r0 top
FID1 "Fiducial" Fiducial10-30 565,195 r0 top
FID2 "Fiducial" Fiducial10-30 565,8365 r90 top
FID3 "Fiducial" Fiducial10-30 7285,8365 r90 top
FID4 "Fiducial" Fiducial10-30 7285,195 r90 top
J1 "61300211121" WURTH_61300211121 715,5955 r90 top
J2 "61300311121" WURTH_61300311121 1775,3125 r0 top
J3 "61300211121" WURTH_61300211121 515,5955 r90 top
J4 "61300311121" WURTH_61300311121 1365,3125 r0 top
J5_1 "971" Keystone_971 185,5425 r0 top (schematic designator J5)
J5_2 "971" Keystone_971 185,7945 r0 top (schematic designator J5)
J6_1 "61300311121" WURTH_61300311121 1385,4045 r0 top (schematic designator J6)
J6_2 "61300311121" WURTH_61300311121 1385,6565 r0 top (schematic designator J6)
J7_1 "61300311121" WURTH_61300311121 1385,4965 r0 top (schematic designator J7)
J7_2 "61300311121" WURTH_61300311121 1385,7485 r0 top (schematic designator J7)
J8_1 "972" Keystone_972 185,4625 r0 top (schematic designator J8)
J8_2 "972" Keystone_972 185,7145 r0 top (schematic designator J8)
J9_1 "TESTPOINT_2Pos" "HIRSCHMANN_973 582-101" 7385,3605 r0 top (schematic designator J9)
J9_2 "TESTPOINT_2Pos" "HIRSCHMANN_973 582-101" 7385,6125 r0 top (schematic designator J9)
J10_1 "Suggest using a net name here" Harwin_H3492-01 6435,4325 r180 top (schematic designator J10)
J10_2 "Suggest using a net name here" Harwin_H3492-01 6435,6845 r180 top (schematic designator J10)
J11_1 "Suggest using a net name here" Harwin_H3492-01 6755,4325 r180 top (schematic designator J11)
J11_2 "Suggest using a net name here" Harwin_H3492-01 6755,6845 r180 top (schematic designator J11)
J12_1 "TESTPOINT_2Pos" "HIRSCHMANN_973 582-100" 7385,4165 r0 top (schematic designator J12)
J12_2 "TESTPOINT_2Pos" "HIRSCHMANN_973 582-100" 7385,6685 r0 top (schematic designator J12)
J13_1 "TESTPOINT_2Pos" "HIRSCHMANN_973 582-101" 7385,4845 r0 top (schematic designator J13)
J13_2 "TESTPOINT_2Pos" "HIRSCHMANN_973 582-101" 7385,7365 r0 top (schematic designator J13)
J14_1 "Suggest using a net name here" Harwin_H3492-01 6435,4685 r180 top (schematic designator J14)
J14_2 "Suggest using a net name here" Harwin_H3492-01 6435,7205 r180 top (schematic designator J14)
J15_1 "Suggest using a net name here" Harwin_H3492-01 6755,4685 r0 top (schematic designator J15)
J15_2 "Suggest using a net name here" Harwin_H3492-01 6755,7205 r0 top (schematic designator J15)
J16_1 "TESTPOINT_2Pos" "HIRSCHMANN_973 582-100" 7385,5405 r0 top (schematic designator J16)
J16_2 "TESTPOINT_2Pos" "HIRSCHMANN_973 582-100" 7385,7925 r0 top (schematic designator J16)
J17_1 "61300311121" WURTH_61300311121 1740,4370 r180 top (schematic designator J17)
J17_2 "61300311121" WURTH_61300311121 1740,6890 r180 top (schematic designator J17)
J18_1 "61300311121" WURTH_61300311121 1115,2575 r0 top (schematic designator J18)
J18_2 "61300311121" WURTH_61300311121 2045,2575 r0 top (schematic designator J18)
J19 "TESTPOINT_2Pos" "HIRSCHMANN_973 582-101" 7385,1760 r0 top
J20 "TESTPOINT_2Pos" "HIRSCHMANN_973 582-100" 7385,2110 r0 top
L1 "LPS6235-334MLB" LPS6235 1285,1025 r0 top
L2 "XPL2010-501MLB" XPL2010 1545,1035 r90 top
L3 "LPS4012-105MLB" LPS4012 1985,1005 r0 top
L4 "XPL2010-501MLB" XPL2010 2225,1035 r90 top
L5_1 "SER2918H-103KL" SER2918H 3915,4005 r90 top (schematic designator L5)
L5_2 "SER2918H-103KL" SER2918H 3915,6525 r90 top (schematic designator L5)
L6_1 "SER2918H-103KL" SER2918H 5595,3765 r270 top (schematic designator L6)
L6_2 "SER2918H-103KL" SER2918H 5595,6285 r270 top (schematic designator L6)
L7_1 "SER2918H-103KL" SER2918H 5595,5245 r90 top (schematic designator L7)
L7_2 "SER2918H-103KL" SER2918H 5595,7765 r90 top (schematic designator L7)
L8_1 "SER2918H-103KL" SER2918H 3915,5005 r270 top (schematic designator L8)
L8_2 "SER2918H-103KL" SER2918H 3915,7525 r270 top (schematic designator L8)
L9 "SER2918H-103KL" SER2918H 4825,2475 r180 top
L10 "100nH" IHLP-2525AH 4525,1755 r270 top
L11 "SER2918H-103KL" SER2918H 4825,1035 r180 top
Q1 "2N7002E" SOT-23 375,1895 r90 top
Q2 "2N7002E" SOT-23 375,1115 r90 top
Q3 "SQD50N06-09L" DPAK 5765,2835 r180 bottom
Q4 "SQD50N06-09L" DPAK 5765,2395 r180 bottom
Q5 "SQD50N06-09L" DPAK 5705,1955 r0 bottom
Q6 "CSD17570Q5B" TRANS_NexFET_Q5B 7295,2105 r270 bottom
Q7 "SQD50N06-09L" DPAK 5765,955 r180 bottom
Q8 "SQD50N06-09L" DPAK 5765,1395 r180 bottom
Q9 "SQD50N06-09L" DPAK 5705,515 r0 bottom
Q10 "CSD17570Q5B" TRANS_NexFET_Q5B 7530,2105 r270 bottom
R1 "CRCW060347K5FKEA" 0603 485,1895 r90 top
R2 "CRCW06033K32FKEA" 0603 375,2015 r0 top
R3 "CRCW060310K0FKEA" 0603 505,2495 r0 top
R4 "CRCW0603100RFKEA" 0603 375,1775 r180 top
R5 "CRCW060380K6FKEA" 0603 625,2675 r270 top
R6 "CRCW060310K0FKEA" 0603 505,2775 r0 top
R7 "CRCW060347K5FKEA" 0603 375,995 r0 top
R8 "CRCW06033K32FKEA" 0603 375,1235 r0 top
R9 "CRCW060349R9FKEA" 0603 1565,485 r90 top
R10 "CRCW06031K00FKEA" 0603 1325,485 r90 top
R11 "CRCW060314K7FKEA" 0603 1405,485 r270 top
R12 "CRCW060311K0FKEA" 0603 875,955 r270 top
R13 "CRCW06032K94FKEA" 0603 765,955 r270 top
R14 "CRCW06032K94FKEA" 0603 655,955 r270 top
R15 "CRCW0603200RFKEA" 0603 545,955 r270 top
R16 "CRCW06031K00FKEA" 0603 2205,515 r0 top
R17 "CRCW060349R9FKEA" 0603 2205,435 r180 top
R18 "CRCW060314K7FKEA" 0603 2005,475 r270 top
R19_1 "CRCW0603100RFKEA" 0603 1655,4525 r0 top (schematic designator R19)
R19_2 "CRCW0603100RFKEA" 0603 1655,7045 r0 top (schematic designator R19)
R20_1 "CRCW0603100RFKEA" 0603 215,4115 r270 bottom (schematic designator R20)
R20_2 "CRCW0603100RFKEA" 0603 215,6635 r270 bottom (schematic designator R20)
R21_1 "CRCW040210K0FKED" 0402 1385,4325 r0 bottom (schematic designator R21)
R21_2 "CRCW040210K0FKED" 0402 1385,6845 r0 bottom (schematic designator R21)
R22_1 "CRCW060313K7FKEA" 0603 935,5195 r270 top (schematic designator R22)
R22_2 "CRCW060313K7FKEA" 0603 935,7715 r270 top (schematic designator R22)
R23_1 "CRCW06030000Z0EA" 0603 345,5215 r0 bottom (schematic designator R23)
R23_2 "CRCW06030000Z0EA" 0603 345,7735 r0 bottom (schematic designator R23)
R24_1 "CRCW0603100KFKEA" 0603 715,3875 r270 bottom (schematic designator R24)
R24_2 "CRCW0603100KFKEA" 0603 715,6395 r270 bottom (schematic designator R24)
R25_1 "CRCW060310K0FKEA" 0603 905,4765 r180 top (schematic designator R25)
R25_2 "CRCW060310K0FKEA" 0603 905,7285 r180 top (schematic designator R25)
R26_1 "CRCW0603100RFKEA" 0603 1655,4605 r0 top (schematic designator R26)
R26_2 "CRCW0603100RFKEA" 0603 1655,7125 r0 top (schematic designator R26)
R27_1 "CRCW040210K0FKED" 0402 1385,4205 r180 bottom (schematic designator R27)
R27_2 "CRCW040210K0FKED" 0402 1385,6725 r180 bottom (schematic designator R27)
R28_1 "CRCW060320K0FKEA" 0603 1065,4665 r180 top (schematic designator R28)
R28_2 "CRCW060320K0FKEA" 0603 1065,7185 r180 top (schematic designator R28)
R29_1 "PTD902-2015F-A103" Bourns_PTD902 25,3845 r270 top (schematic designator R29)
R29_2 "PTD902-2015F-A103" Bourns_PTD902 25,6365 r270 top (schematic designator R29)
R30_1 "CRCW060310K0FKEA" 0603 935,3675 r180 top (schematic designator R30)
R30_2 "CRCW060310K0FKEA" 0603 935,6195 r180 top (schematic designator R30)
R31_1 "CRCW060324K3FKEA" 0603 935,3755 r180 top (schematic designator R31)
R31_2 "CRCW060324K3FKEA" 0603 935,6275 r180 top (schematic designator R31)
R32_1 "CRCW06030000Z0EA" 0603 145,3915 r90 bottom (schematic designator R32)
R32_2 "CRCW06030000Z0EA" 0603 145,6435 r90 bottom (schematic designator R32)
R33_1 "CRCW060320K0FKEA" 0603 1065,4765 r180 top (schematic designator R33)
R33_2 "CRCW060320K0FKEA" 0603 1065,7285 r180 top (schematic designator R33)
R34_1 "CRCW06034K53FKEA" 0603 1035,5195 r270 top (schematic designator R34)
R34_2 "CRCW06034K53FKEA" 0603 1035,7715 r270 top (schematic designator R34)
R35_1 "CRCW06036K81FKEA" 0603 905,4665 r0 top (schematic designator R35)
R35_2 "CRCW06036K81FKEA" 0603 905,7185 r0 top (schematic designator R35)
R36_1 "CRCW0603100RFKEA" 0603 1655,4805 r0 top (schematic designator R36)
R36_2 "CRCW0603100RFKEA" 0603 1655,7325 r0 top (schematic designator R36)
R37_1 "CRCW0603100RFKEA" 0603 325,4115 r270 bottom (schematic designator R37)
R37_2 "CRCW0603100RFKEA" 0603 325,6635 r270 bottom (schematic designator R37)
R38_1 "CRCW040210K0FKED" 0402 1385,4685 r0 bottom (schematic designator R38)
R38_2 "CRCW040210K0FKED" 0402 1385,7205 r0 bottom (schematic designator R38)
R39_1 "CRCW040210K0FKED" 0402 1385,4805 r180 bottom (schematic designator R39)
R39_2 "CRCW040210K0FKED" 0402 1385,7325 r180 bottom (schematic designator R39)
R40_1 "CRCW06030000Z0EA" 0603 345,4415 r0 bottom (schematic designator R40)
R40_2 "CRCW06030000Z0EA" 0603 345,6935 r0 bottom (schematic designator R40)
R41_1 "CRCW0603100KFKEA" 0603 715,4015 r90 bottom (schematic designator R41)
R41_2 "CRCW0603100KFKEA" 0603 715,6535 r90 bottom (schematic designator R41)
R42_1 "CRCW0603100RFKEA" 0603 1655,4725 r0 top (schematic designator R42)
R42_2 "CRCW0603100RFKEA" 0603 1655,7245 r0 top (schematic designator R42)
R43_1 "CRCW060310K0FKEA" 0603 985,4215 r180 top (schematic designator R43)
R43_2 "CRCW060310K0FKEA" 0603 985,6735 r180 top (schematic designator R43)
R44_1 "CRCW060324K3FKEA" 0603 985,4135 r180 top (schematic designator R44)
R44_2 "CRCW060324K3FKEA" 0603 985,6655 r180 top (schematic designator R44)
R45_1 "CRCW06033R32FKEA" 0603 4835,3545 r90 bottom (schematic designator R45)
R45_2 "CRCW06033R32FKEA" 0603 4835,6065 r90 bottom (schematic designator R45)
R46_1 "CRCW06033R32FKEA" 0603 2005,4145 r180 bottom (schematic designator R46)
R46_2 "CRCW06033R32FKEA" 0603 2005,6665 r180 bottom (schematic designator R46)
R47_1 "CRCW06033R32FKEA" 0603 6355,3945 r270 bottom (schematic designator R47)
R47_2 "CRCW06033R32FKEA" 0603 6355,6465 r270 bottom (schematic designator R47)
R48_1 "CRCW06033R32FKEA" 0603 2010,4145 r180 top (schematic designator R48)
R48_2 "CRCW06033R32FKEA" 0603 2010,6665 r180 top (schematic designator R48)
R49_1 "CRCW060322K1FKEA" 0603 2005,4340 r0 bottom (schematic designator R49)
R49_2 "CRCW060322K1FKEA" 0603 2005,6860 r0 bottom (schematic designator R49)
R50_1 "CRCW06033R32FKEA" 0603 6355,5065 r90 bottom (schematic designator R50)
R50_2 "CRCW06033R32FKEA" 0603 6355,7585 r90 bottom (schematic designator R50)
R51_1 "CRCW06033R32FKEA" 0603 2005,4870 r180 bottom (schematic designator R51)
R51_2 "CRCW06033R32FKEA" 0603 2005,7390 r180 bottom (schematic designator R51)
R52_1 "CRCW06033R32FKEA" 0603 4835,5465 r270 bottom (schematic designator R52)
R52_2 "CRCW06033R32FKEA" 0603 4835,7985 r270 bottom (schematic designator R52)
R53_1 "CRCW060310K0FKEA" 0603 2005,4405 r0 bottom (schematic designator R53)
R53_2 "CRCW060310K0FKEA" 0603 2005,6925 r0 bottom (schematic designator R53)
R54_1 "CRCW06030000Z0EA" 0603 2005,4470 r0 bottom (schematic designator R54)
R54_2 "CRCW06030000Z0EA" 0603 2005,6990 r0 bottom (schematic designator R54)
R55_1 "CRCW060310K0FKEA" 0603 1455,2285 r90 top (schematic designator R55)
R55_2 "CRCW060310K0FKEA" 0603 2385,2285 r90 top (schematic designator R55)
R56_1 "CRCW060310K0FKEA" 0603 915,1755 r90 top (schematic designator R56)
R56_2 "CRCW060310K0FKEA" 0603 1845,1755 r90 top (schematic designator R56)
R57_1 "CRCW060323K7FKEA" 0603 1395,1645 r90 top (schematic designator R57)
R57_2 "CRCW060323K7FKEA" 0603 2325,1645 r90 top (schematic designator R57)
R58_1 "CRCW06031K00FKEA" 0603 1315,1795 r90 top (schematic designator R58)
R58_2 "CRCW06031K00FKEA" 0603 2245,1795 r90 top (schematic designator R58)
R59_1 "CRCW060310K0FKEA" 0603 1335,2285 r270 top (schematic designator R59)
R59_2 "CRCW060310K0FKEA" 0603 2265,2285 r270 top (schematic designator R59)
R60_1 "CRCW0603200KFKEA" 0603 915,1535 r90 top (schematic designator R60)
R60_2 "CRCW0603200KFKEA" 0603 1845,1535 r90 top (schematic designator R60)
R61_1 "CRCW060310K0FKEA" 0603 1315,1495 r270 top (schematic designator R61)
R61_2 "CRCW060310K0FKEA" 0603 2245,1495 r270 top (schematic designator R61)
R62_1 "CRCW0603365KFKEA" 0603 1315,1645 r90 top (schematic designator R62)
R62_2 "CRCW0603365KFKEA" 0603 2245,1645 r90 top (schematic designator R62)
R63_1 "CRCW060310K0FKEA" 0603 775,2285 r270 top (schematic designator R63)
R63_2 "CRCW060310K0FKEA" 0603 1705,2285 r270 top (schematic designator R63)
R64_1 "CRCW060310K0FKEA" 0603 895,2285 r270 top (schematic designator R64)
R64_2 "CRCW060310K0FKEA" 0603 1825,2285 r270 top (schematic designator R64)
R65_1 "CRCW060310K0FKEA" 0603 1115,2315 r180 top (schematic designator R65)
R65_2 "CRCW060310K0FKEA" 0603 2045,2315 r180 top (schematic designator R65)
R66_1 "CRCW060310K0FKEA" 0603 1115,2395 r180 top (schematic designator R66)
R66_2 "CRCW060310K0FKEA" 0603 2045,2395 r180 top (schematic designator R66)
R67 "CRCW06030000Z0EA" 0603 3495,2305 r90 top
R68 "CRCW060330K1FKEA" 0603 3885,3015 r180 top
R69 "CRCW06033R32FKEA" 0603 3885,3085 r180 top
R70 "CRCW06030000Z0EA" 0603 3635,555 r90 top
R71 "CRCW06033R32FKEA" 0603 3835,1195 r90 top
R72 "CRCW06030000Z0EA" 0603 4115,2615 r270 top
R73 "CRCW06030000Z0EA" 0603 4115,865 r270 top
R74 "CRCW0603100KFKEA" 0603 3735,2685 r90 top
R75 "CRCW06030000Z0EA" 0603 4255,2305 r90 top
R76 "CRCW06030000Z0EA" 0603 4255,555 r90 top
R77 "CRCW060349R9FKEA" 0603 3575,2545 r90 top
R78 "CRCW0603100KFKEA" 0603 3575,2685 r270 top
R79 "CRCW06030000Z0EA" 0603 3565,2305 r270 top
R80 "CRCW06037K68FKEA" 0603 3885,2945 r0 top
R81 "CRCW060320K0FKEA" 0603 3425,2305 r90 top
R82 "CRCW060337K4FKEA" 0603 3695,2795 r0 top
R83 "CRCW06030000Z0EA" 0603 3635,2305 r90 top
R84 "CRCW060320K0FKEA" 0603 3565,555 r90 top
R85 "CRCW06033K74FKEA" 0603 3655,2685 r270 top
R86 "CRCW060344K2FKEA" 0603 3575,2835 r270 top
R87 "CRCW20108R20JNEF" 2010 5665,2175 r0 bottom
R88 "ERJ-M1WTF1M5U" 2512 5725,2935 r180 top
R89 "CRCW06031K00FKEA" 0603 7443.5,2440 r180 bottom
R90 "CRCW20108R20JNEF" 2010 5805,2615 r180 bottom
R91 "CRCW06031K00FKEA" 0603 4225,2855 r0 top
R92 "CRCW06031K00FKEA" 0603 4225,2775 r0 top
R93 "CRCW06034R75FKEA" 0603 3925,2305 r270 top
R94 "CRCW06034R75FKEA" 0603 3705,2305 r270 top
R95 "CRCW06034R75FKEA" 0603 4225,2495 r0 top
R96 "ERJ-1TRQJR68U" 2512 4795,1755 r270 top
R97 "CRCW20108R20JNEF" 2010 5665,735 r0 bottom
R98 "ERJ-M1WTF1M5U" 2512 5725,1495 r180 top
R99 "CRCW20108R20JNEF" 2010 5805,1175 r180 bottom
R100 "CRCW06031K00FKEA" 0603 4225,1105 r0 top
R101 "CRCW06031K00FKEA" 0603 4225,1025 r0 top
R102 "CRCW06034R75FKEA" 0603 3705,555 r270 top
R103 "CRCW06034R75FKEA" 0603 3925,555 r270 top
R104 "CRCW06034R75FKEA" 0603 4225,745 r0 top
S1 "431256038716" SW_1825027-2 195,2675 r270 top
U1 "TPS3803-01-Q1" DCK0005A_N 505,2675 r0 top
U2 "LM2841X-Q1" MK06A_N 1365,665 r90 top
U3 "LM2841X-Q1" MK06A_N 2045,665 r90 top
U4 "TPS7A6633-Q1" DGN0008D_N 615,525 r90 top
U5_1 "OPA1662A-Q1" D0008A_N 985,3945 r90 top (schematic designator U5)
U5_2 "OPA1662A-Q1" D0008A_N 985,6465 r90 top (schematic designator U5)
U6_1 "OPA1662AIDGKRQ1" DGK0008A_N 1385,4505 r90 bottom (schematic designator U6)
U6_2 "OPA1662AIDGKRQ1" DGK0008A_N 1385,7025 r90 bottom (schematic designator U6)
U7_1 "OPA1662A-Q1" D0008A_N 985,4965 r90 top (schematic designator U7)
U7_2 "OPA1662A-Q1" D0008A_N 985,7485 r90 top (schematic designator U7)
U8_1 "TPA3251D2" DDV0044D_N 2365,4505 r0 bottom (schematic designator U8)
U8_2 "TPA3251D2" DDV0044D_N 2365,7025 r0 bottom (schematic designator U8)
U9_1 "LM2904-Q1" D0008A_N 1115,1645 r0 top (schematic designator U9)
U9_2 "LM2904-Q1" D0008A_N 2045,1645 r0 top (schematic designator U9)
U10_1 "LM2904-Q1" D0008A_N 1115,2085 r180 top (schematic designator U10)
U10_2 "LM2904-Q1" D0008A_N 2045,2085 r180 top (schematic designator U10)
U11 "LM25122-Q1" PWP0020A_N 3925,2605 r270 top
U12 "LM25122-Q1" PWP0020A_N 3925,865 r270 top

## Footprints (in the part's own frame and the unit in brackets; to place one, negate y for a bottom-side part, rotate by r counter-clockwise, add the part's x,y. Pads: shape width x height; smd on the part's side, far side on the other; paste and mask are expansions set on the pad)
0402 [mm] "0402 from SM-752 data"
  rect 0.8x0.6 smd: 1(-0.6,0) 2(0.6,0)
  silkscreen extent -1.22,-0.52 1.22,0.52, body extent -0.55,-0.3 0.55,0.3, height 0.6
551-0403_Red [mm] "TH, 2-Leads, Body 4.57x4.57mm, Pitch 2.55mm"
  rect 1.65x1.65 hole 1.143: 1(-1.275,1.275)
  round 1.65 hole 1.143: 2(-1.275,-1.275)
  round 1.24 hole 1.24 unplated mask+0: MH1(1.275,1.275) MH2(1.275,-1.275)
  silkscreen extent -2.8,-2.38 2.39,2.39, body extent -2.38,-2.38 6.34,2.39, height 9.02
0603 [mm] "0603 from SM-752 data"
  rect 1x0.95 smd: 1(-0.8,0) 2(0.8,0)
  silkscreen extent -1.52,-0.69 1.52,0.69, body extent -0.87,-0.47 0.87,0.47, height 1
0805_HV [mil] "0805 with 30mil clearance between pads"
  rect 50x63 smd: 1(-40,0) 2(40,0)
  silkscreen extent -74,-40 74,40, body extent -43,-29 43,29, height 57
1206 [mm] "1206 from SM-752 data"
  rect 1.3x1.85 smd: 1(-1.45,0) 2(1.45,0)
  silkscreen extent -2.4,-1.21 2.4,1.21, body extent -1.7,-0.9 1.7,0.9, height 1.35
1210 [mm] "1210 from SM-752 data"
  rect 1.3x2.7 smd: 1(-1.45,0) 2(1.45,0)
  silkscreen extent -2.32,-1.57 2.32,1.57, body extent -1.7,-1.35 1.7,1.35, height 1.35
2010 [mm] "Chip Capacitor, Body 5.08x2.54mm, IPC Medium Density"
  rect 1.6x2.7 smd: 1(-2.3,0) 2(2.3,0)
  silkscreen extent -3.42,-1.65 3.42,1.65, body extent -2.73,-1.45 2.73,1.45, height 1.66
2512 [mm] "Chip Resistor, Body 6.3x3.2mm, IPC Medium Density"
  rect 1.3x3.4 smd: 1(-2.95,0) 2(2.95,0)
  silkscreen extent -1.9,-1.6 1.9,1.6, body extent -3.22,-1.67 3.22,1.67, height 0.71
Bourns_PTD902 [mm] "TH, 6-Leads, Body 9.5x9.65mm, Pitch 2.5mm"
  rect 1.5x1.5 hole 1: 1(-2.5,5)
  round 1.5 hole 1: 1'(-2.5,7.5) 2(0,5) 2'(0,7.5) 3(2.5,5) 3'(2.5,7.5)
  silkscreen extent -5.25,0.15 4.75,9.65, body extent -4.75,-15 4.75,9.65, height 11.3
D0008A_N [mm] "SOIC, 8-Leads, Body 4.9x3.9mm, Pitch 1.27mm, IPC Medium Density"
  oval 1.45x0.6 smd: 1(-2.725,1.905) 2(-2.725,0.635) 3(-2.725,-0.635) 4(-2.725,-1.905) 5(2.725,-1.905) 6(2.725,-0.635) 7(2.725,0.635) 8(2.725,1.905)
  silkscreen extent -3.3,-2.5 0.9,2.5, body extent -3,-2.45 3,2.45, height 1.63
DCK0005A_N [mm] "SOT353, 5-Leads, Body 2x1.3mm, Pitch 0.65mm, Lead Span 2.1mm, IPC Medium Density"
  rrect25% 0.85x0.4 smd: 1(-1.125,0.65) 2(-1.125,0) 3(-1.125,-0.65) 4(1.125,-0.65) 5(1.125,0.65)
  silkscreen extent -1.48,-1.02 0.55,1.1, body extent -1.14,-1 1.14,1, height 0.95
DDV0044D_N [mm] "SOP, 44-Leads, Body 14.1x6.2mm, Pitch 0.635mm, IPC Medium Density"
  oval 1.4x0.4 smd: 1(-3.8,6.667) 2(-3.8,6.032) 3(-3.8,5.397) 4(-3.8,4.763) 5(-3.8,4.127) 6(-3.8,3.492) 7(-3.8,2.857) 8(-3.8,2.222) 9(-3.8,1.587) 10(-3.8,0.953) 11(-3.8,0.318) 12(-3.8,-0.318) 13(-3.8,-0.953) 14(-3.8,-1.587) 15(-3.8,-2.222) 16(-3.8,-2.857) 17(-3.8,-3.492) 18(-3.8,-4.127) 19(-3.8,-4.763) 20(-3.8,-5.397) 21(-3.8,-6.032) 22(-3.8,-6.667) 23(3.8,-6.667) 24(3.8,-6.032) 25(3.8,-5.397) 26(3.8,-4.763) 27(3.8,-4.127) 28(3.8,-3.492) 29(3.8,-2.857) 30(3.8,-2.222) 31(3.8,-1.587) 32(3.8,-0.953) 33(3.8,-0.318) 34(3.8,0.318) 35(3.8,0.953) 36(3.8,1.587) 37(3.8,2.222) 38(3.8,2.857) 39(3.8,3.492) 40(3.8,4.127) 41(3.8,4.763) 42(3.8,5.397) 43(3.8,6.032) 44(3.8,6.667)
  silkscreen extent -4.35,-7.05 2.7,7.12, body extent -4.06,-7 4.06,7, height 1.2
DGK0008A_N [mm] "TSOP, 8-Leads, Body 3x3mm, Pitch 0.65mm, IPC Medium Density"
  oval 1.35x0.45 smd: 1(-2.225,0.975) 2(-2.225,0.325) 3(-2.225,-0.325) 4(-2.225,-0.975) 5(2.225,-0.975) 6(2.225,-0.325) 7(2.225,0.325) 8(2.225,0.975)
  silkscreen extent -2.75,-1.55 0.95,1.55, body extent -2.45,-1.5 2.45,1.5, height 0.96
DGN0008D_N [mm] "TSOP, 8-Leads, Body 3x3mm, Pitch 0.65mm, Thermal Pad 1.89x1.57mm, IPC Medium Density"
  rrect100% 1.35x0.45 smd: 1(-2.225,0.975) 2(-2.225,0.325) 3(-2.225,-0.325) 4(-2.225,-0.975) 5(2.225,-0.975) 6(2.225,-0.325) 7(2.225,0.325) 8(2.225,0.975)
  rrect6% 1.57x1.89 smd: 9(0,0)
  silkscreen extent -2.73,-1.55 0.95,1.55, body extent -2.46,-1.5 2.46,1.5, height 1.1
DPAK [mm] "D-PAK, 3-Pads, Body 6.22x6.73mm (max), TO-252AA using nominal STEP model"
  rrect6% 2.6x1.6 smd: 1(-3.4,2.28) 3(-3.4,-2.28)
  rrect2% 6.2x5.8 smd paste-2.9: 4(3.4,0)
  silkscreen extent -4.5,-3.3 4.7,3.28, body extent -3.86,-3.29 5.84,3.29, height 2.48
Fiducial10-30 [mm]
  round 1 smd mask+1: 1(0,0)
  Top keep-out circle w1.678: c0,0 r0.75
Harwin_H3492-01 [mm] "Pin Receptacle, Dia 4 mm, TH"
  round 5.12 hole 4.12: 1(0,0)
  silkscreen extent -2.9,-2.9 2.9,2.9, body extent -2.35,-2.36 2.37,2.36, height 0.8
"HIRSCHMANN_973 582-100" [mil] "Hirschmann Automation and Control GmbH"
  rect 85x85 hole 55: 1(-364.17,0)
  round 85 hole 55: 2(364.17,0)
  body extent -414,-157 413,157, height 413
"HIRSCHMANN_973 582-101" [mil] "Hirschmann Automation and Control GmbH"
  rect 85x85 hole 55: 1(-364.17,0)
  round 85 hole 55: 2(364.17,0)
  body extent -414,-157 413,157, height 413
IHLP-2525AH [mm] "Vishay Dale"
  rect 1.83x3.43 smd: 1(-2.77,0) 2(2.77,0)
  silkscreen extent -3.7,-3.4 3.7,3.4, body extent -3.62,-3.36 3.62,3.36, height 1.8
Keystone_971 [mm] "PC Mount Phono Jack-Red, TH"
  round 2.6 hole 2.08: 1(0,0) 3(9.8,0)
  round 3.4 hole 2.87: 4(8,-5.3)
  round 0 hole 1.98 unplated: M1(0,3.745) M2(0,-3.745)
  round 0 hole 2.08 unplated: M3(6.5,0)
  silkscreen extent -3.99,-5.01 10.03,5.01, body extent -13.31,-5.44 10.05,5, height 13.02
Keystone_972 [mm] "RCA Jack, Black, R/A, TH"
  round 2.6 hole 2.08: 1(0,0) 3(9.8,0)
  round 3.4 hole 2.87: 4(8,-5.3)
  round 0 hole 1.98 unplated: M1(0,3.745) M2(0,-3.745)
  round 0 hole 2.08 unplated: M3(6.5,0)
  silkscreen extent -3.99,-5.01 10.03,5.01, body extent -13.32,-5.41 10.03,5.03, height 12.51
LPS4012 [mm] "Coilcraft recommended land pattern.  Document 433-2, rev 10/20/08"
  rect 0.7x3.124 smd: 1(-1.881,0) 2(1.881,0)
  rect 0.902x0.801 smd rot 135: 1(-1.592,-1.605) 2(1.592,1.605)
  rect 0.902x0.801 smd rot 45: 1(-1.592,1.605) 2(1.592,-1.605)
  rect 0.812x0.7 smd: 1(-1.168,-1.85) 1(-1.168,1.85) 2(1.168,-1.85) 2(1.168,1.85)
  silkscreen extent -3.26,-2.6 2.55,2.6, body extent -2.05,-2.05 2.05,2.05, height 1.22
LPS6235 [mm] "Coilcraft recommended land pattern.  Document 587-2, rev 10/17/08"
  rect 1.2x4.25 smd: 1(-2.7,0) 2(2.7,0)
  rect 1.68x1.6 smd rot 135: 1(-2.126,-2.151) 2(2.126,2.151)
  rect 1.68x1.6 smd rot 45: 1(-2.126,2.151) 2(2.126,-2.151)
  rect 1.125x1.2 smd: 1(-1.562,-2.7) 1(-1.562,2.7) 2(1.562,-2.7) 2(1.562,2.7)
  silkscreen extent -3.7,-3.7 3.7,3.7, body extent -3.1,-3.1 3.1,3.1, height 3.52
MK06A_N [mm] "SOT23, 6-Leads, Body 3.0x1.7mm, Pitch 0.95mm, Lead Span 2.9mm, IPC Medium Density"
  rect 1.1x0.65 smd: 1(-1.2,0.95) 2(-1.2,0) 3(-1.2,-0.95) 4(1.2,-0.95) 5(1.2,0) 6(1.2,0.95)
  silkscreen extent -1.32,-1.55 0.25,1.95, body extent -0.9,-1.55 0.9,1.55, height 1
PHE426_1800x950x1750 [mm] "TH, 2-Leads, 18x9.5mm, Pin Spacing 15mm"
  round 1.55 hole 1.05: 1(-7.5,0) 2(7.5,0)
  silkscreen extent -9,-4.75 9,4.75, body extent -9,-4.75 9,4.75, height 17.5
PW_1800x2000 [mm] "TH, 2-Leads, Dia 18mm, Pin Spacing 7.5mm"
  rect 1.55x1.55 hole 1.05: 1(-3.75,0)
  round 1.55 hole 1.05: 2(3.75,0)
  silkscreen extent -9.25,-9.25 9.25,9.25, body extent -9.18,-9.23 9.22,9.24, height 22.01
PWP0020A_N [mm] "TSOP, 20-Leads, Body 6.5x4.4mm, Pitch 0.65mm, Exposed Pad, IPC Medium Density"
  rrect100% 1.4x0.45 smd: 1(-2.95,2.925) 2(-2.95,2.275) 3(-2.95,1.625) 4(-2.95,0.975) 5(-2.95,0.325) 6(-2.95,-0.325) 7(-2.95,-0.975) 8(-2.95,-1.625) 9(-2.95,-2.275) 10(-2.95,-2.925) 11(2.95,-2.925) 12(2.95,-2.275) 13(2.95,-1.625) 14(2.95,-0.975) 15(2.95,-0.325) 16(2.95,0.325) 17(2.95,0.975) 18(2.95,1.625) 19(2.95,2.275) 20(2.95,2.925)
  rrect3% 3x4.2 smd: 21(0,0)
  silkscreen extent -3.55,-3.3 1.5,3.4, body extent -3.21,-3.25 3.21,3.25, height 1
R82_720x250x650 [mm] "TH, 2-Leads, Body 7.2x2.5mm, Lead Spacing 5mm"
  round 1.3 hole 0.8: 1(-2.5,0) 2(2.5,0)
  silkscreen extent -3.7,-1.3 3.7,1.3, body extent -3.7,-1.3 3.7,1.3, height 6.6
R82_720x720x1300 [mm] "TH, 2-Leads, Body 7.2x7.2mm, Lead Spacing 5mm"
  round 1.4 hole 0.9: 1(-2.5,0) 2(2.5,0)
  silkscreen extent -3.75,-3.65 3.75,3.65, body extent -3.75,-3.65 3.75,3.65, height 13.1
SER2918H [mm] "COILCRAFT"
  rect 5.59x5.33 smd: 1(-14.355,5.075) 2(-14.455,-5.075)
  rect 6.35x5.28 smd: 3(8.25,0)
  silkscreen extent -11.04,-14 10.81,13.9, body extent -16.7,-14.05 11.22,13.85, height 17.82
SMC [mil] "Molded Diode, 2-Leads, Body 6.9x5.8mm, IPC Medium Density, based on OnSemi component dimensions and land patterns"
  rect 110x150 smd: 1(-140.49,0) 2(140.49,0)
  silkscreen extent -221,-124 189,123, body extent -156,-116 156,116, height 91
SOD-123F [mm] "NXP recommended land pattern"
  rect 1.2x1.2 smd paste-0.05: 1(-1.4,0) 2(1.4,0)
  silkscreen extent -2.64,-1.12 2.01,1.12, body extent -1.8,-0.85 1.8,0.85, height 1.2
SOD-123FL [mm] "Copied from SOD-123"
  rect 0.915x1.22 smd: 1(-1.637,0) 2(1.637,0)
  silkscreen extent -2.74,-1.16 1.68,1.16, body extent -1.9,-0.9 1.9,0.9, height 1
sod-323 [mm] "NXP recommended land pattern"
  rect 0.6x0.6 smd paste-0.05: 1(-1.1,0) 2(1.1,0)
  silkscreen extent -2.06,-0.86 1.53,0.86, body extent -1.3,-0.67 1.3,0.68, height 1.1
SOT-23 [mm] "SOT23, 3-Leads, Body 2.9x1.3mm, Pitch 0.95mm, Lead Span 2.5mm, IPC Medium Density"
  rrect50% 1x0.6 smd: 1(-1.2,0.95) 2(-1.2,-0.95) 3(1.2,0)
  silkscreen extent -1.63,-1.5 0.7,1.5, body extent -1.16,-1.45 1.21,1.45, height 1
SW_1825027-2 [mm] "TH, 2-Leads, Body 7.11x7.16mm"
  round 1.5 hole 0.99: 1(-2.25,-1.245) 2(2.25,-1.245)
  round 1.8 hole 1.3: MH1(-3.505,1.245) MH2(3.505,1.245)
  silkscreen extent -3.56,-3.83 3.56,-0.14, body extent -4.2,-4.38 4.2,2.77, height 7.01
TRANS_NexFET_Q5B [mm] "TI recommended land pattern (nominal) November 2012"
  rect 1.372x0.71 smd paste-0.4: 1(-2.776,1.905) 2(-2.776,0.635) 3(-2.776,-0.635) 4(-2.776,-1.905)
  rect 0.59x0.71 smd paste-0.3: 5(2.776,-1.905) 6(2.776,-0.635) 7(2.776,0.635) 8(2.776,1.905)
  Top region: -1.106,2.26 2.744,2.26 2.744,-2.26 -1.106,-2.26
  silkscreen extent -3.38,-2.7 3,2.7, body extent -3.23,-2.55 2.87,2.55, height 1.06
WL-SMCW_GREEN [mm] "WURTH"
  rect 0.8x0.8 smd: 1(-0.8,0) 2(0.8,0)
  silkscreen extent -1.9,-0.8 1.2,0.8, body extent -0.85,-0.45 0.85,0.45, height 0.8
WURTH_61300211121 [mm] "Header, 2.54mm, 2x1, TH"
  rect 1.65x1.65 hole 1.15: 1(-1.27,0)
  round 1.65 hole 1.15: 2(1.27,0)
  silkscreen extent -2.54,-1.27 2.54,1.6, body extent -2.54,-1.27 2.54,1.27, height 8.54
WURTH_61300311121 [mm] "Header, 2.54mm, 3x1, TH"
  rect 1.65x1.65 hole 1.15: 1(-2.54,0)
  round 1.65 hole 1.15: 2(0,0) 3(2.54,0)
  silkscreen extent -3.81,-1.27 3.81,1.6, body extent -3.81,-1.27 3.81,1.27, height 8.54
XPL2010 [mm] "Coilcraft recommended land pattern Document 646-2 Revised 3/28/11"
  rect 1.04x2.2 smd: 1(-0.725,0) 2(0.725,0)
  silkscreen extent -1.52,-1.4 1.52,1.4, body extent -1.05,-1.1 1.05,1.1, height 1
